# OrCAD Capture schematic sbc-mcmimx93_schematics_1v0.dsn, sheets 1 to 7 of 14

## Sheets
1 10  Ethernet connectos: size B; title: SBC-MCM93  10. Ethernet connectos; rev: 1.0; note: 8000233000; note: 17 HaYetsira Street; note: Yokneam Illit, Israel 2069208
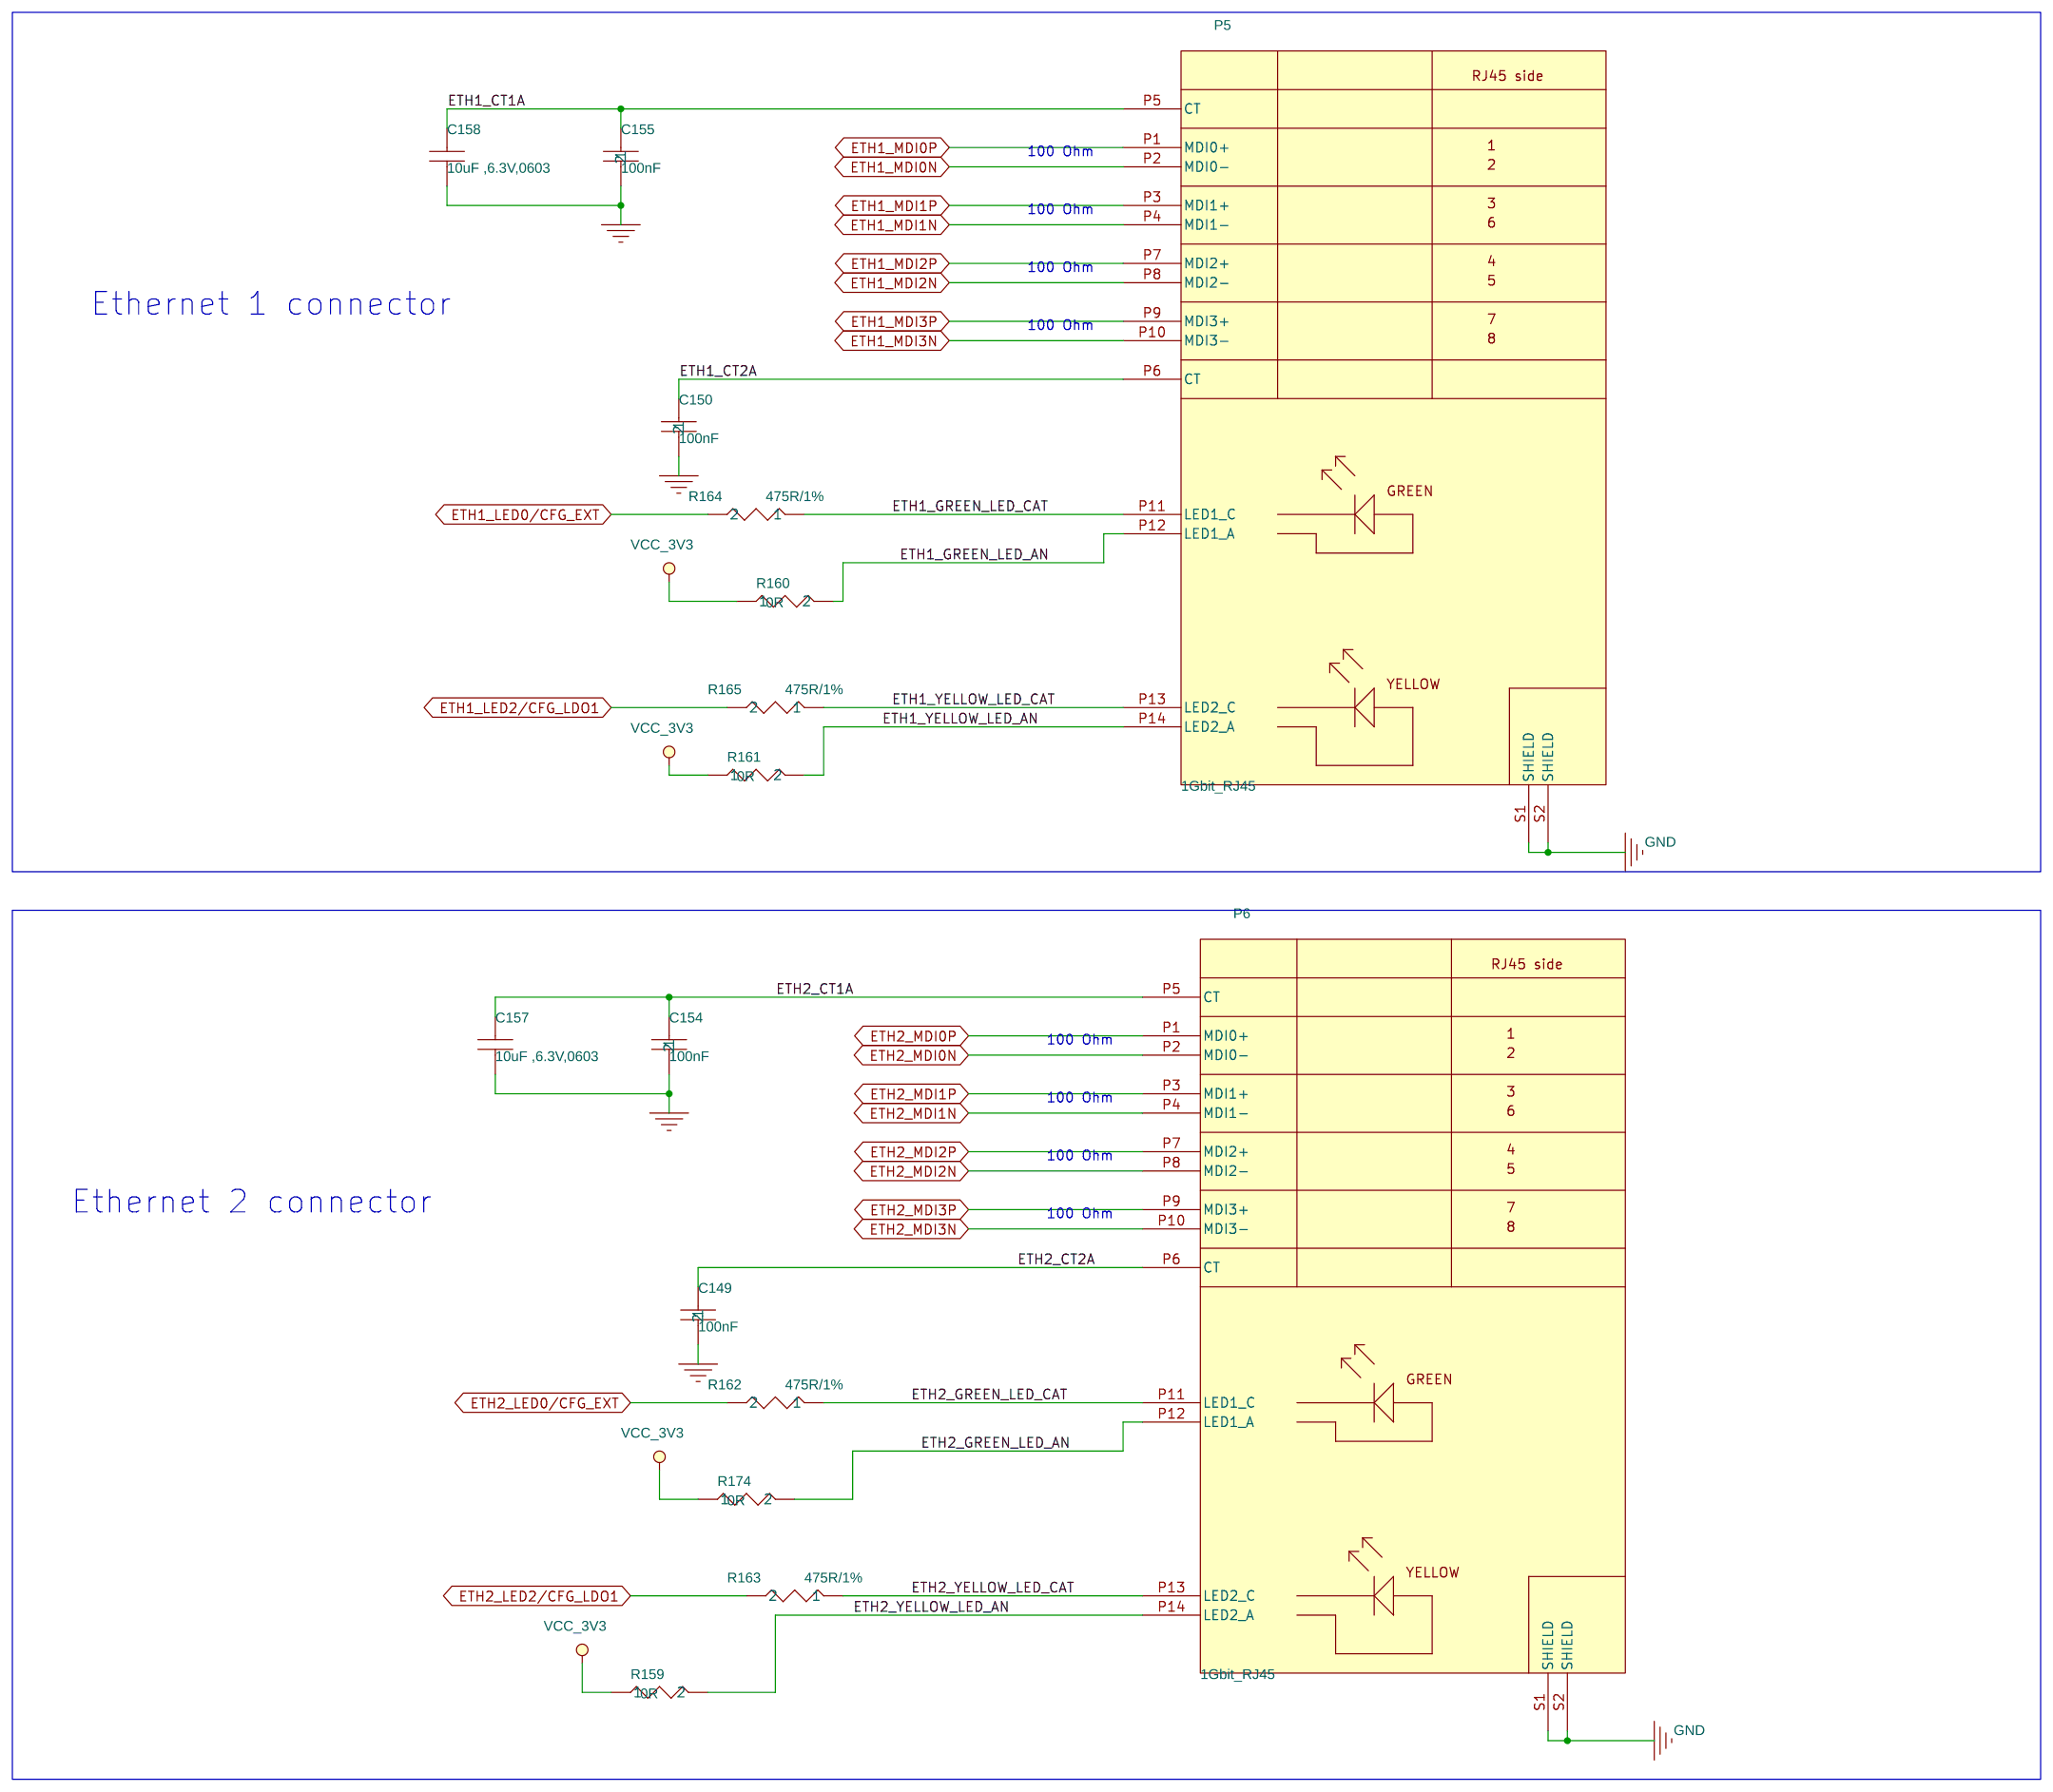
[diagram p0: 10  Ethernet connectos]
2 01 Index and Block Diagram: title: SBC-MCM93   01. INDEX AND BLOCK DIAGRAM
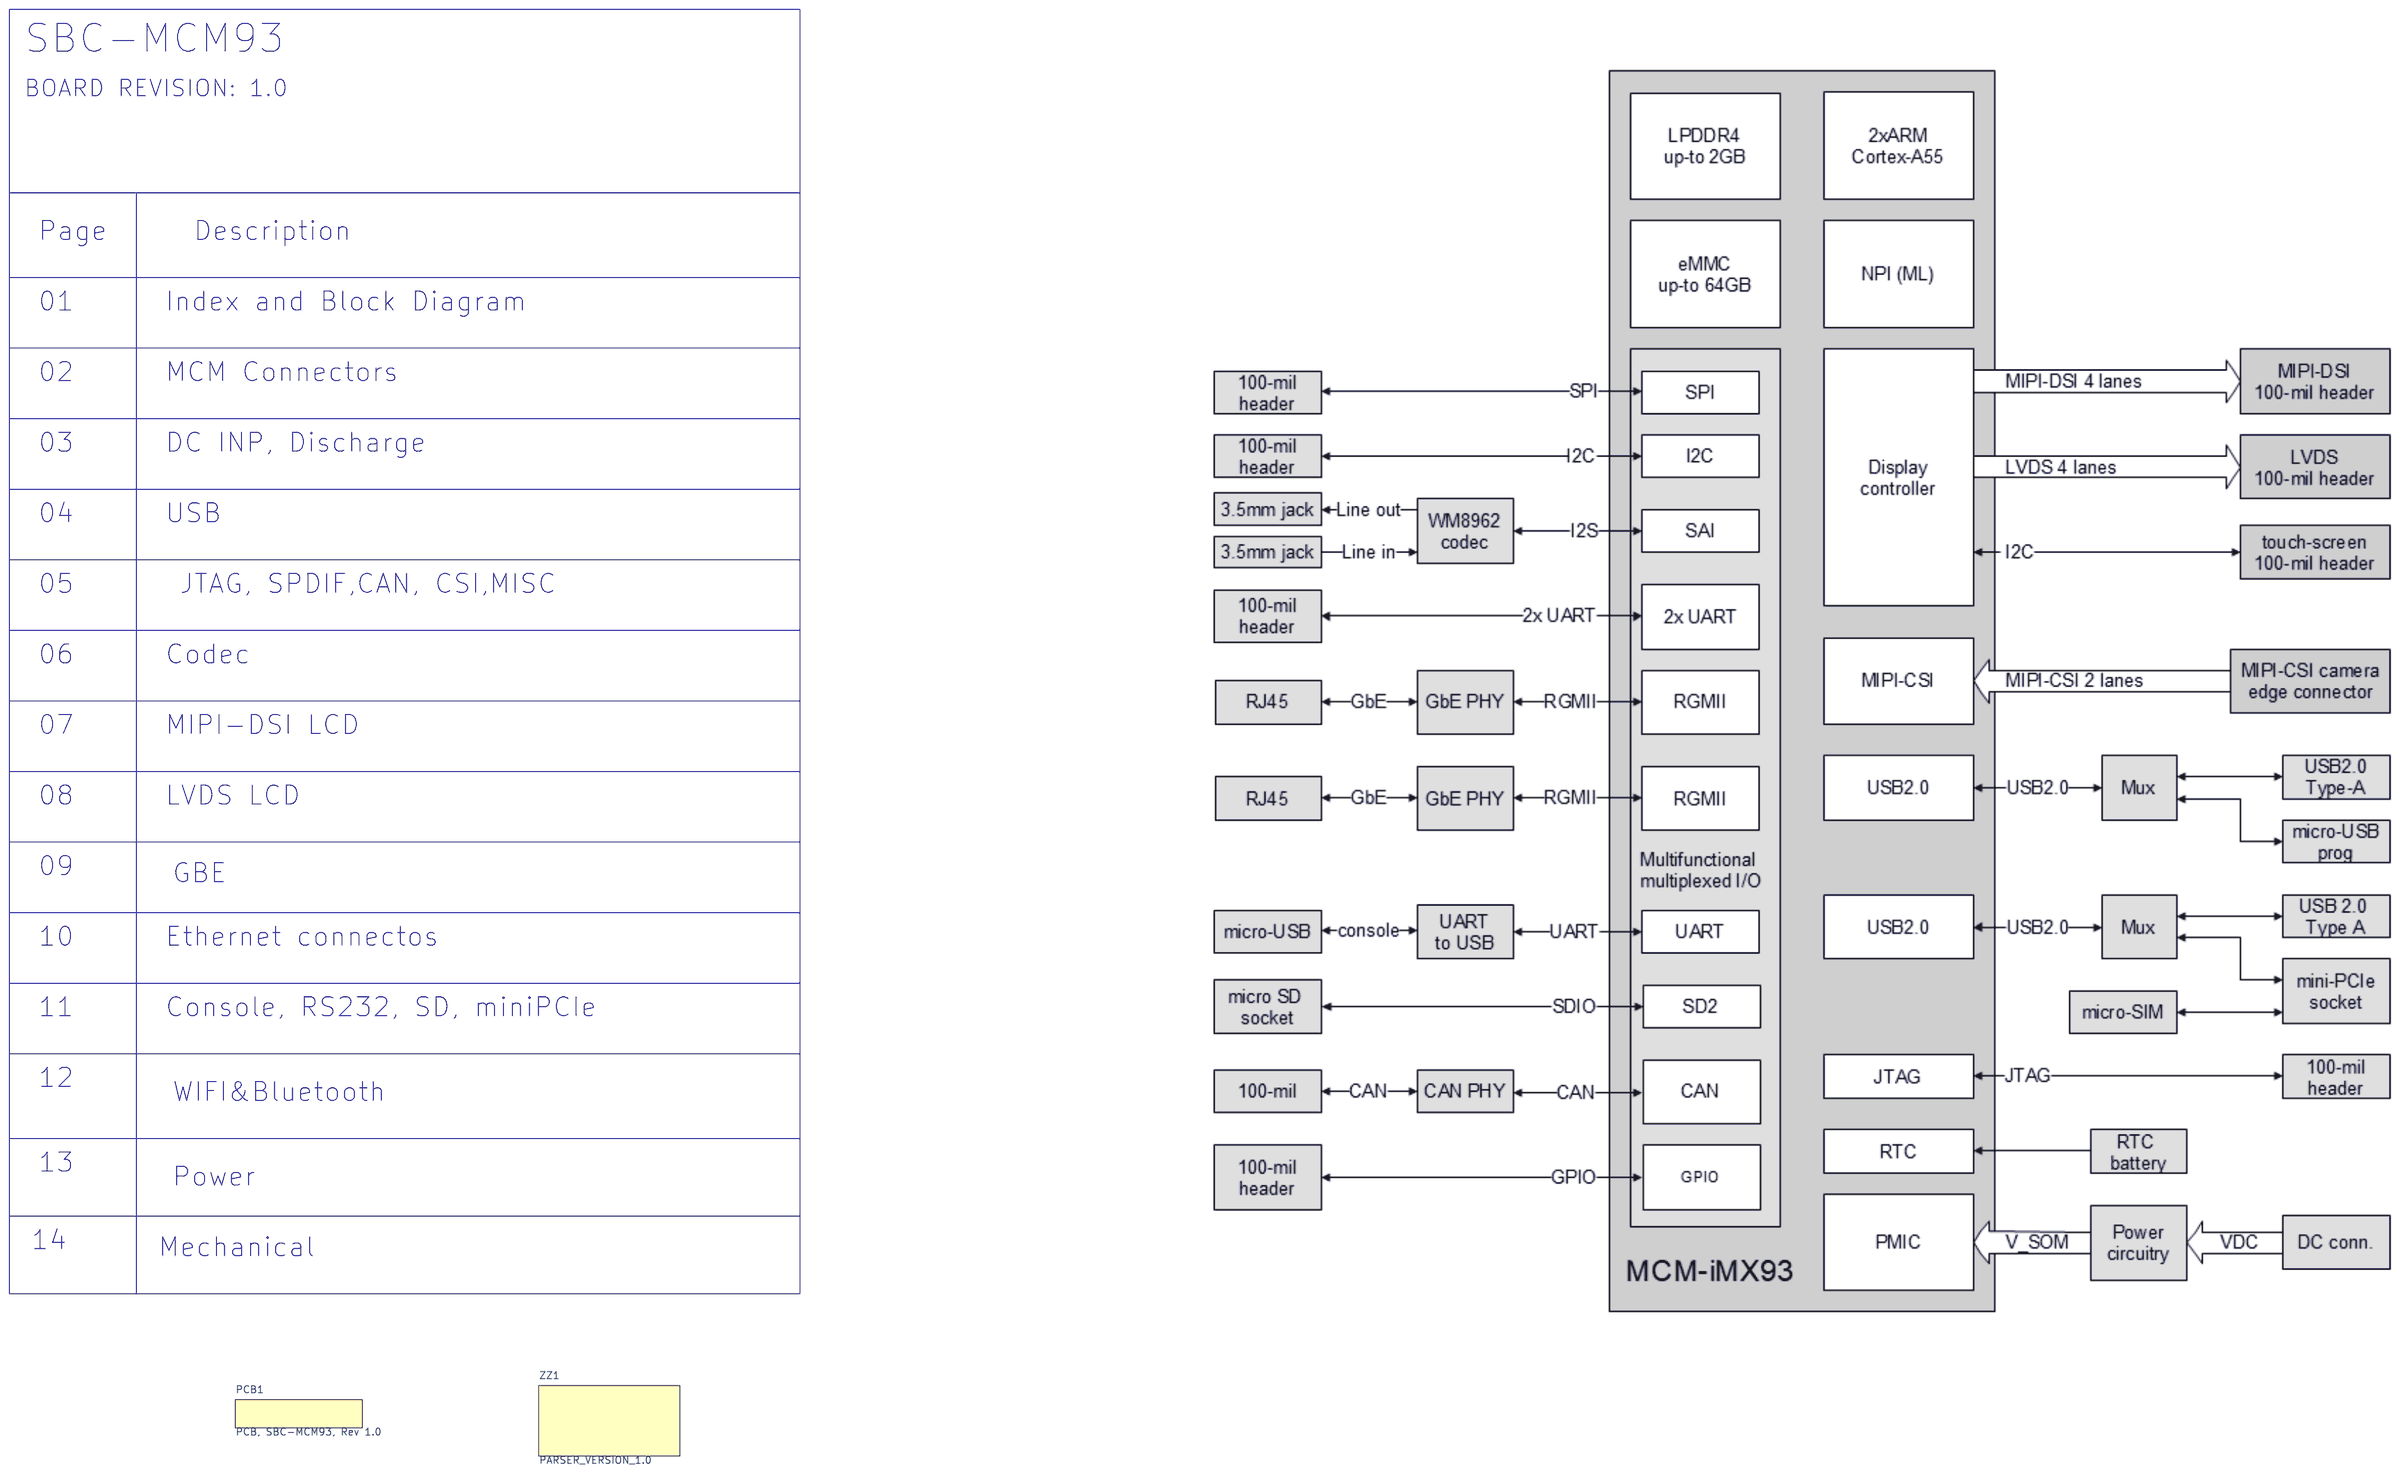
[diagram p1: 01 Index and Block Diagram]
3 03 DC INP, Discharge: size B; title: SBC-MCM93     03 DC INP, Discharge; company: CompuLab Ltd.  (972) 4 8238567
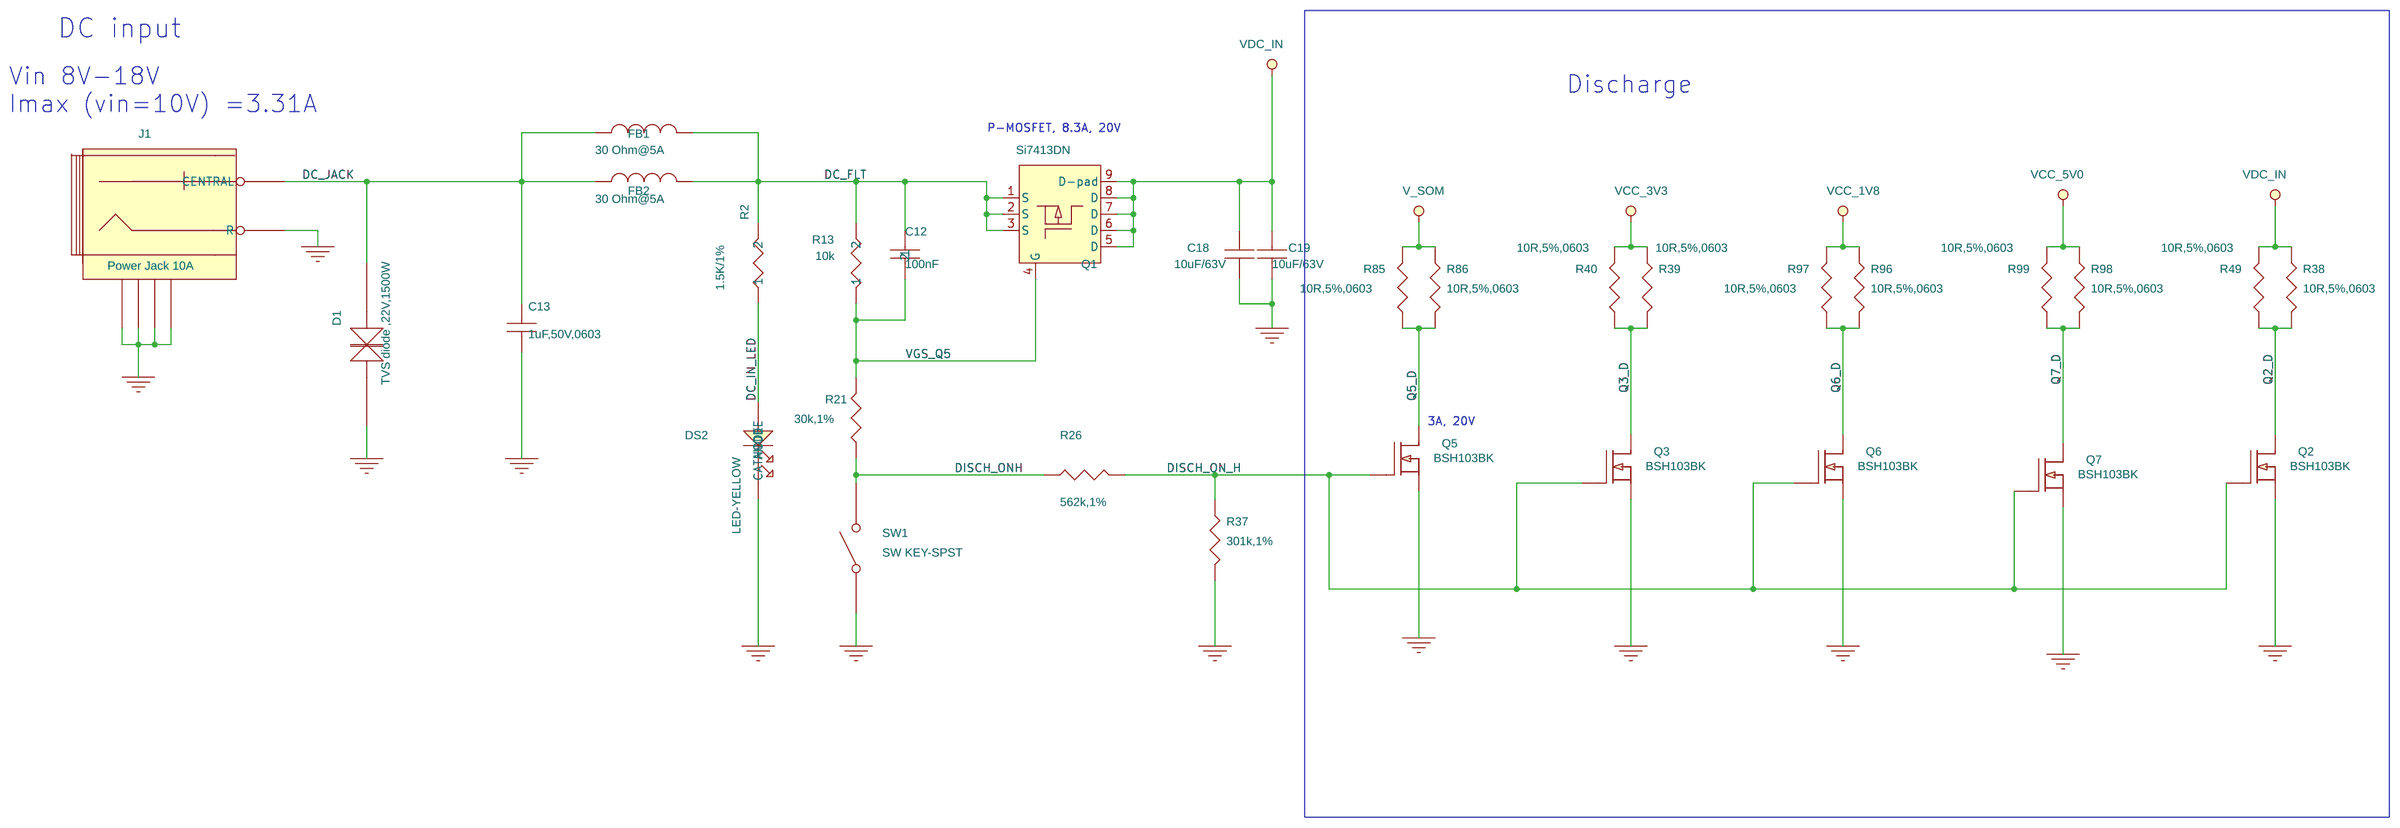
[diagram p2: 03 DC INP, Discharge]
4 02. Carrier Board interface MCM: size C; title: SBC-MCM93     02. Carrier Board interface MCM
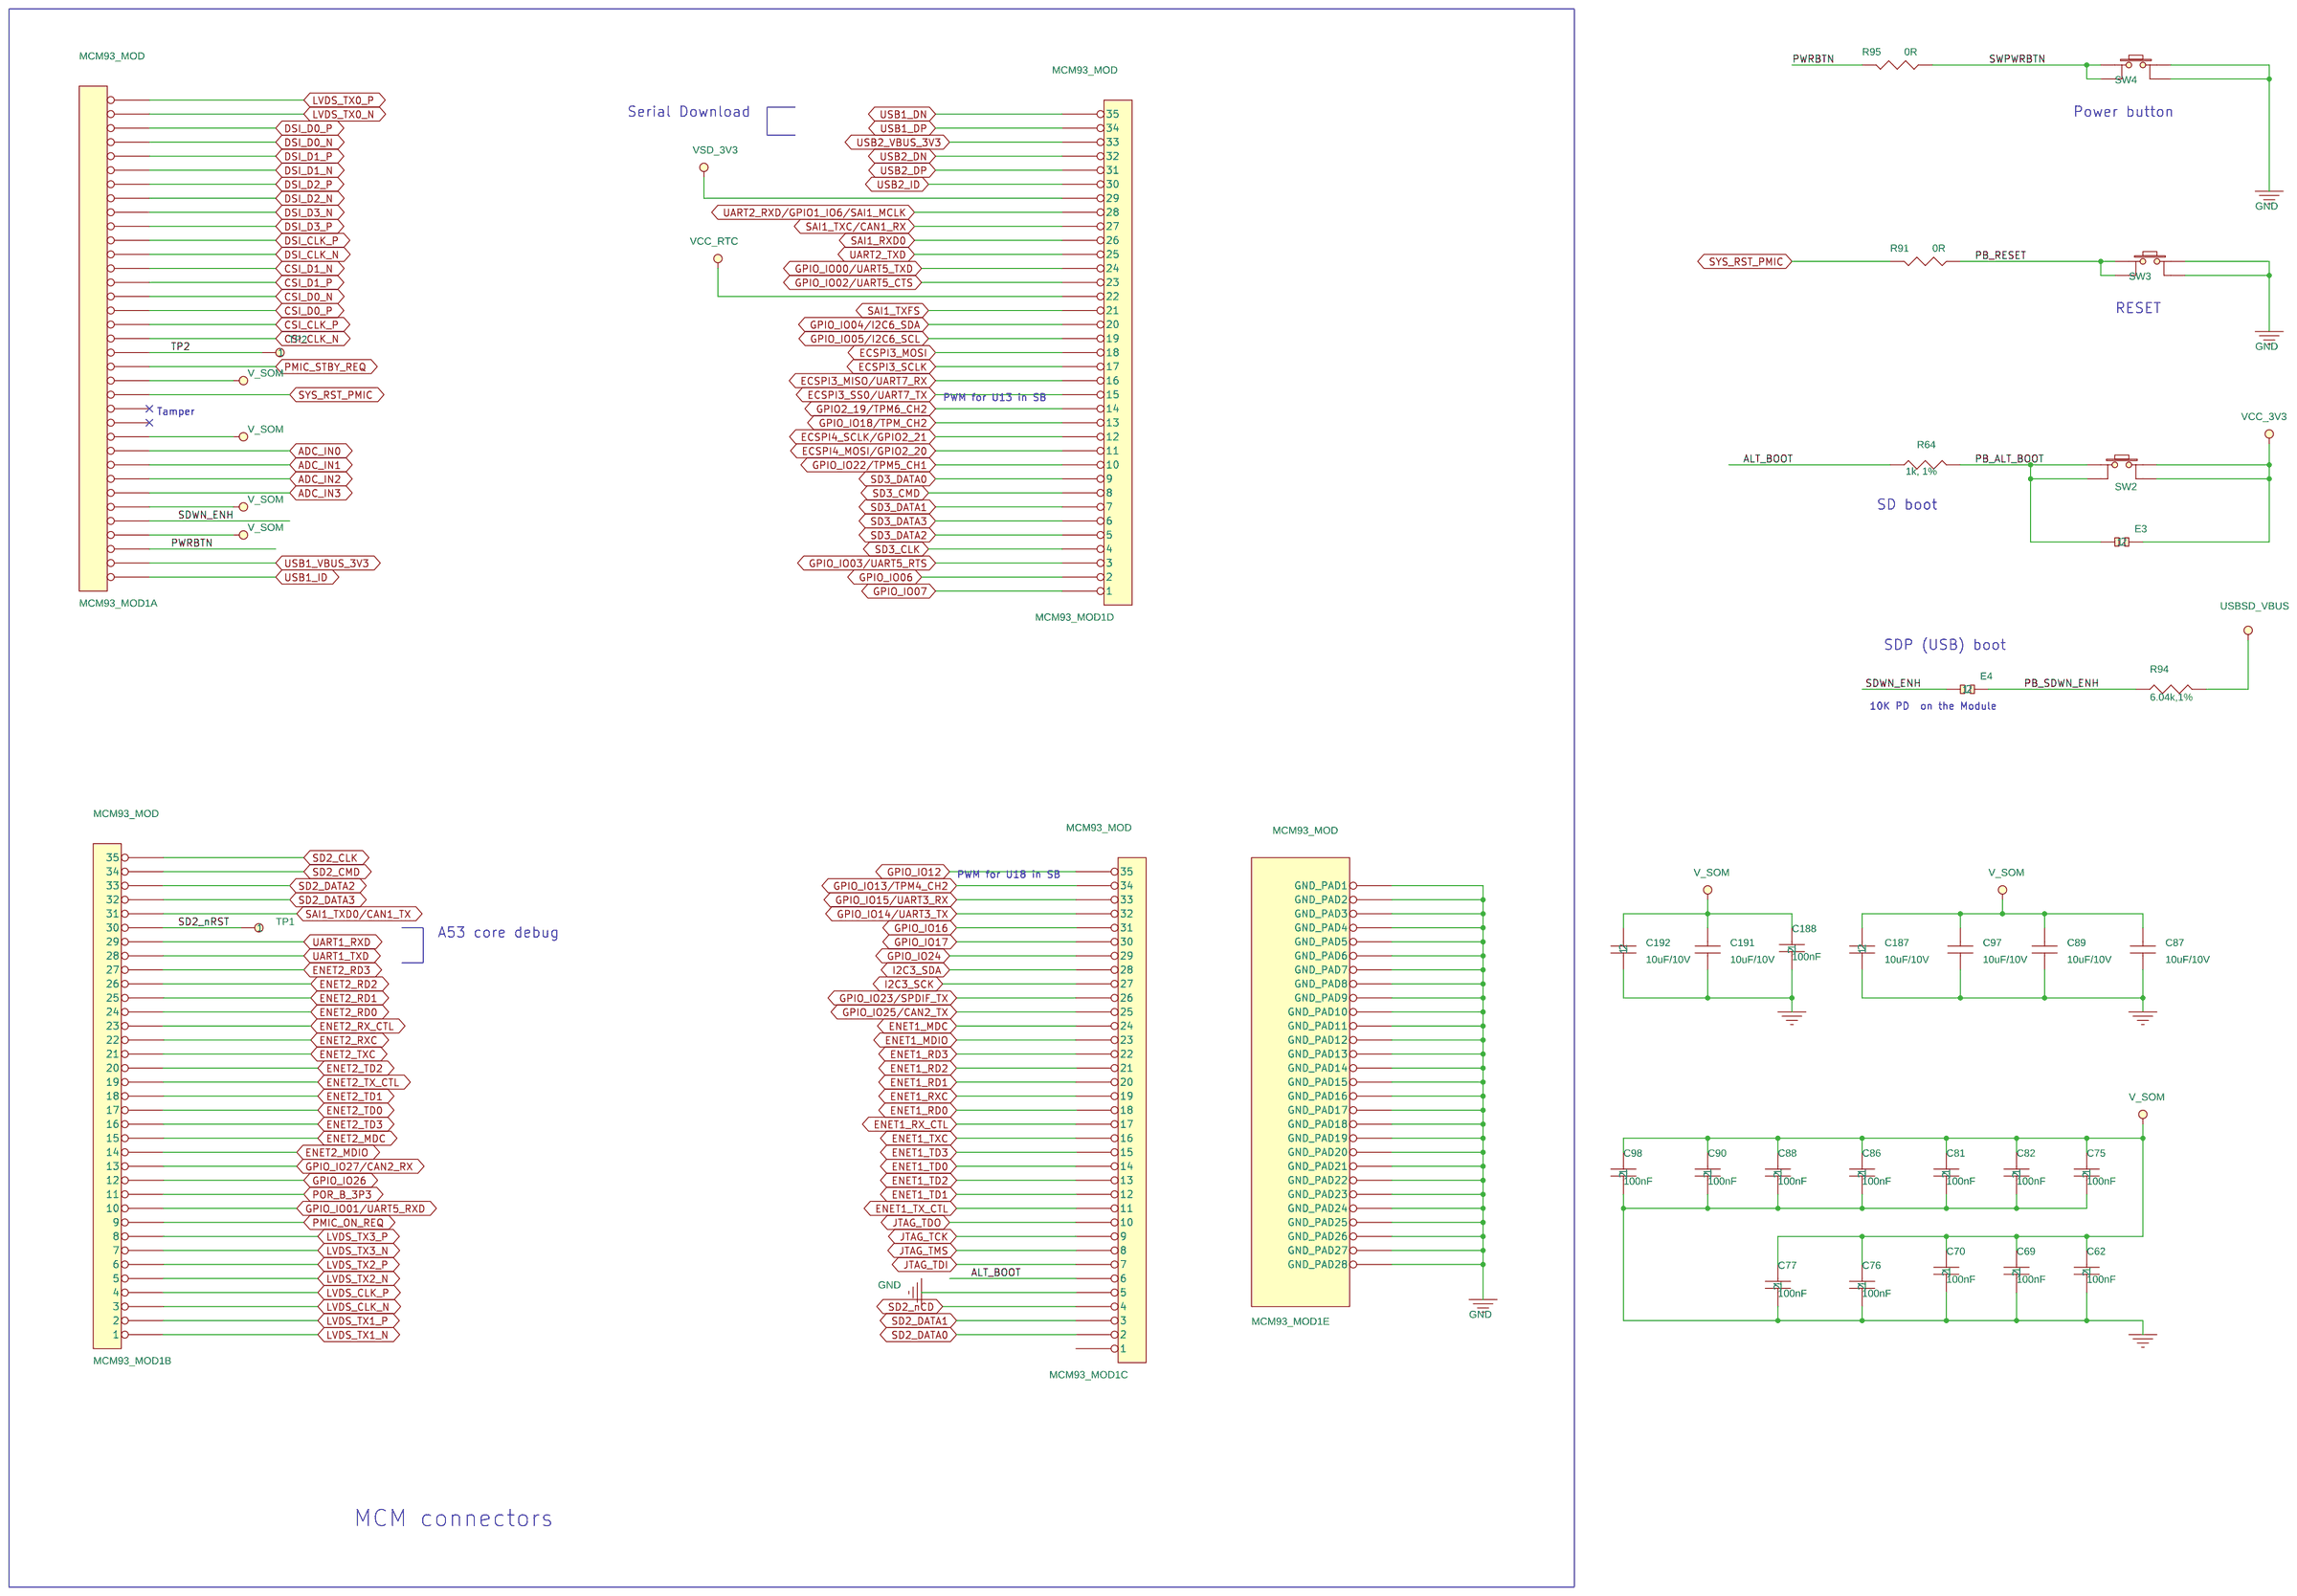
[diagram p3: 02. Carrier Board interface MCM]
5 04 USB: size C; title: SBC-MCM93    04. USB
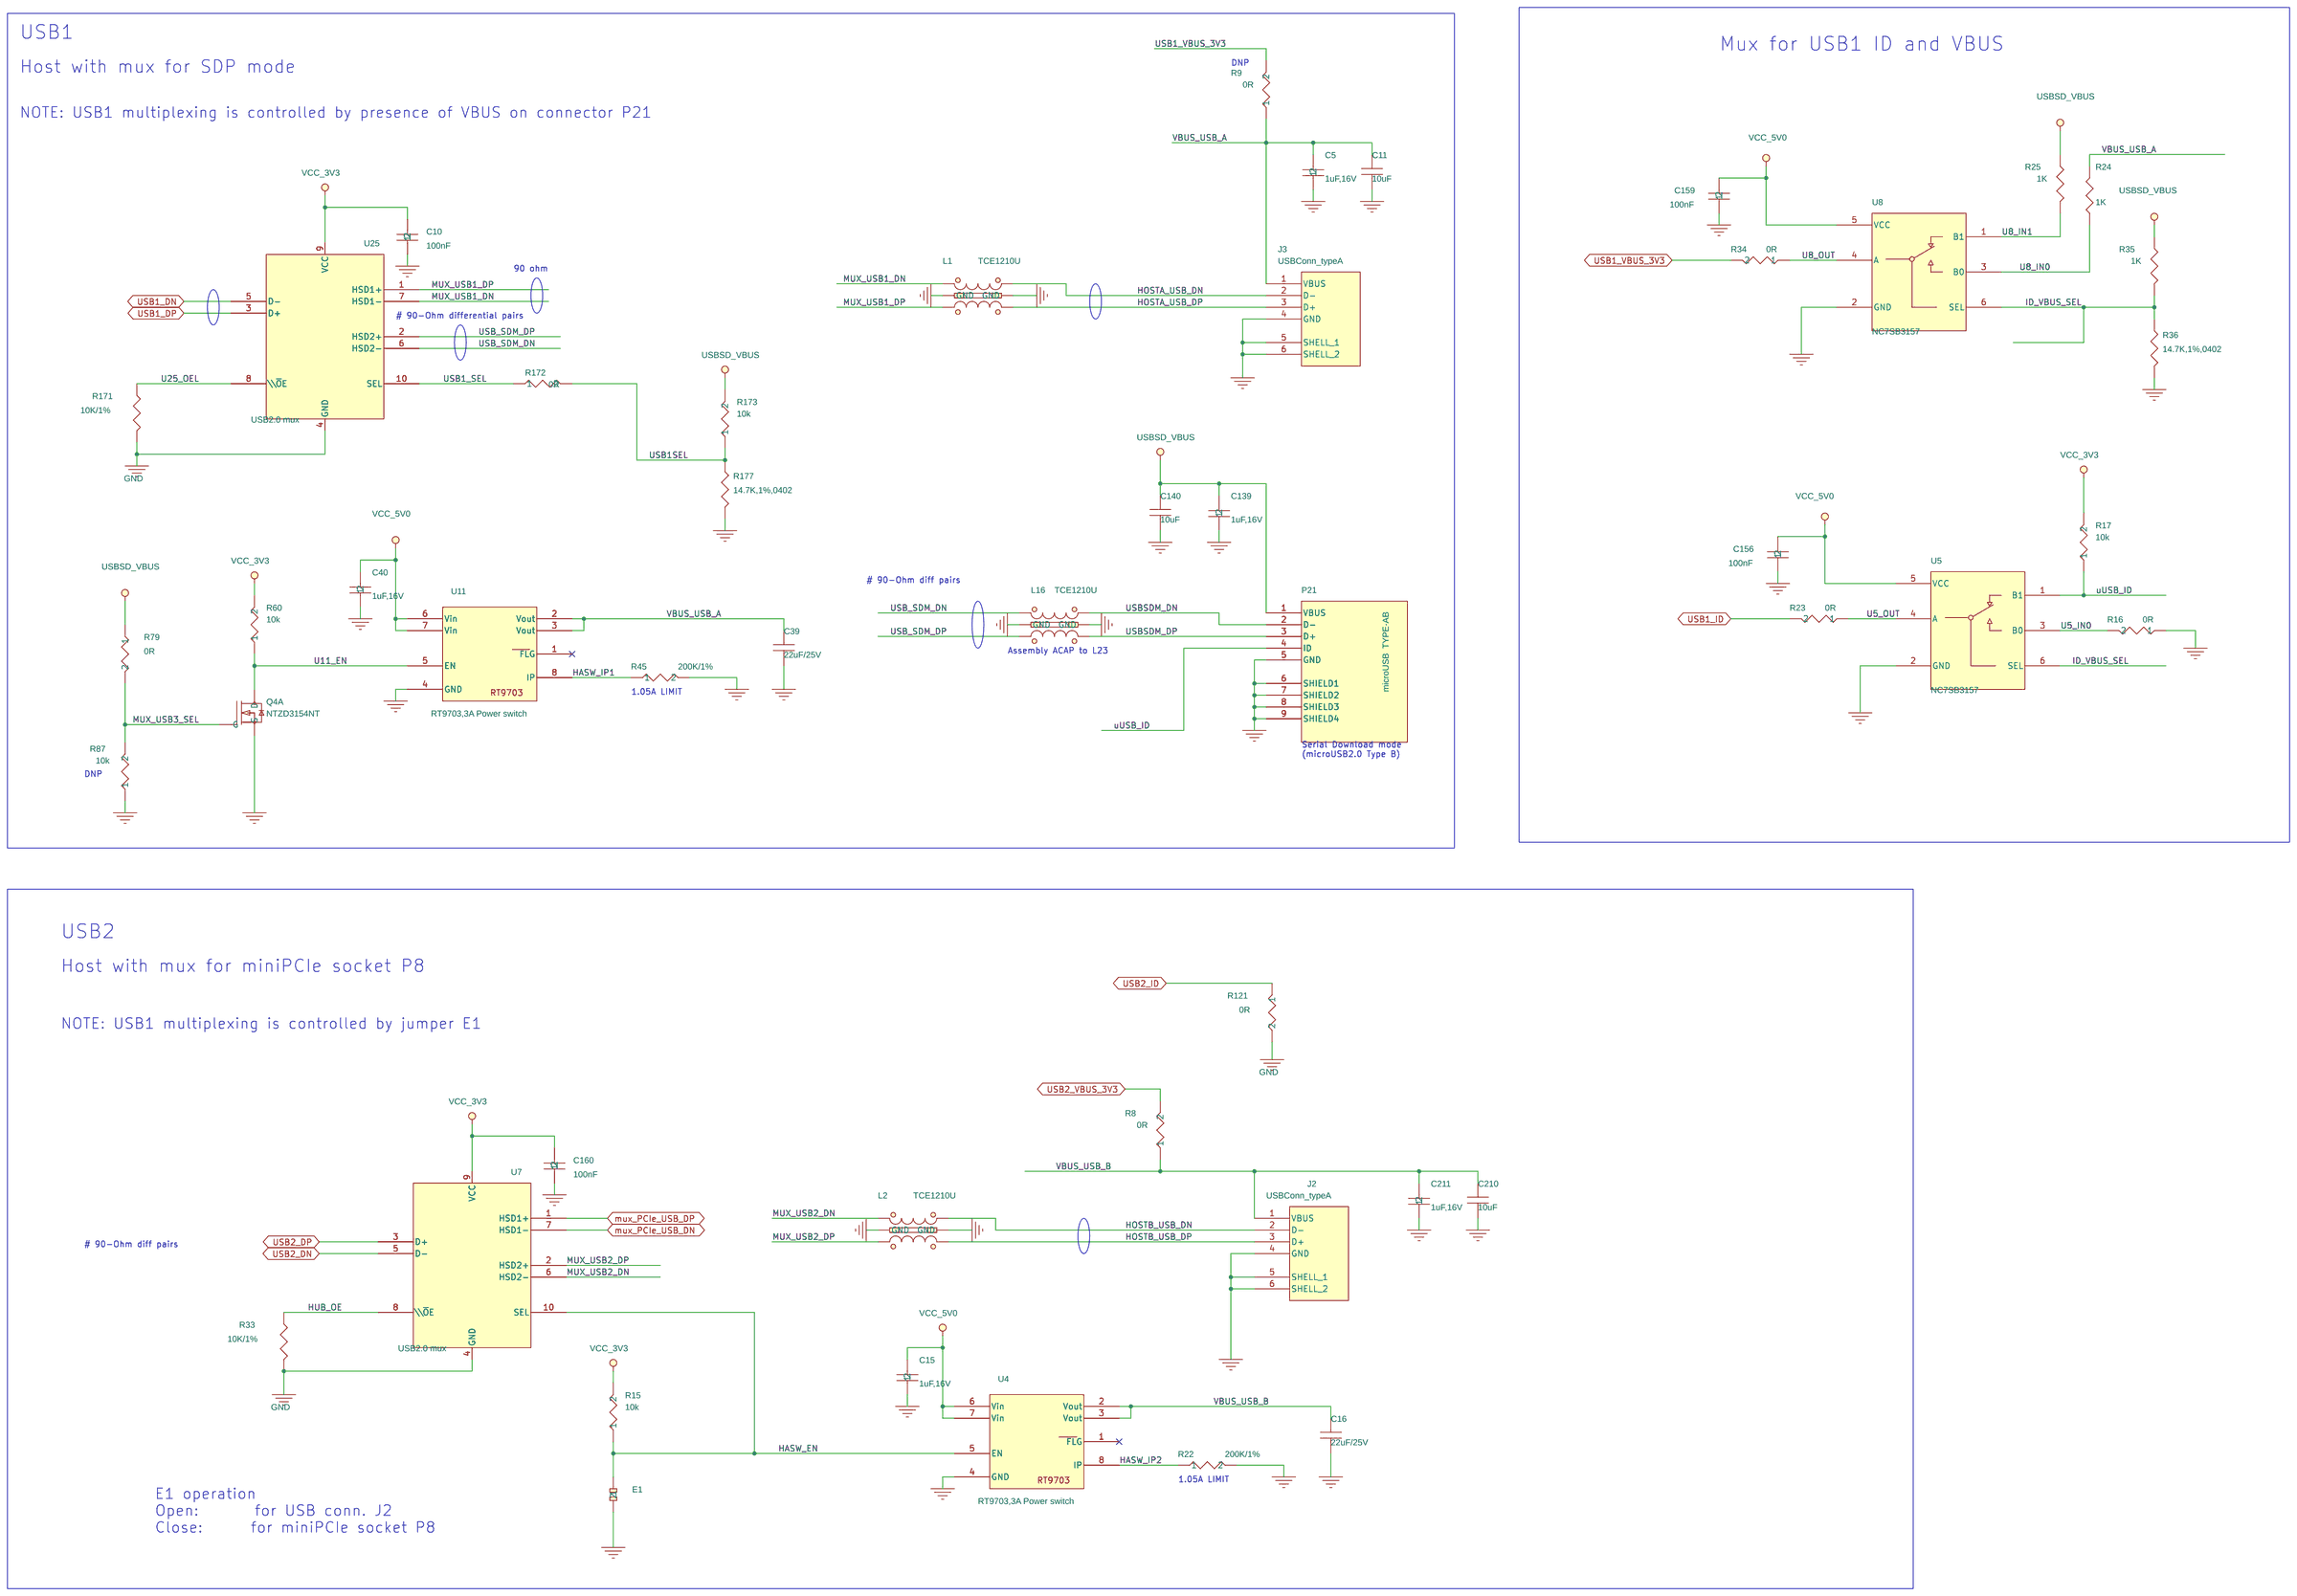
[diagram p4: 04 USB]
6 05  JTAG, SPDIF,CAN, CSI,MISC: size C; title: SBC-MCM93      05.  JTAG, SPDIF,CAN, CSI,MISC
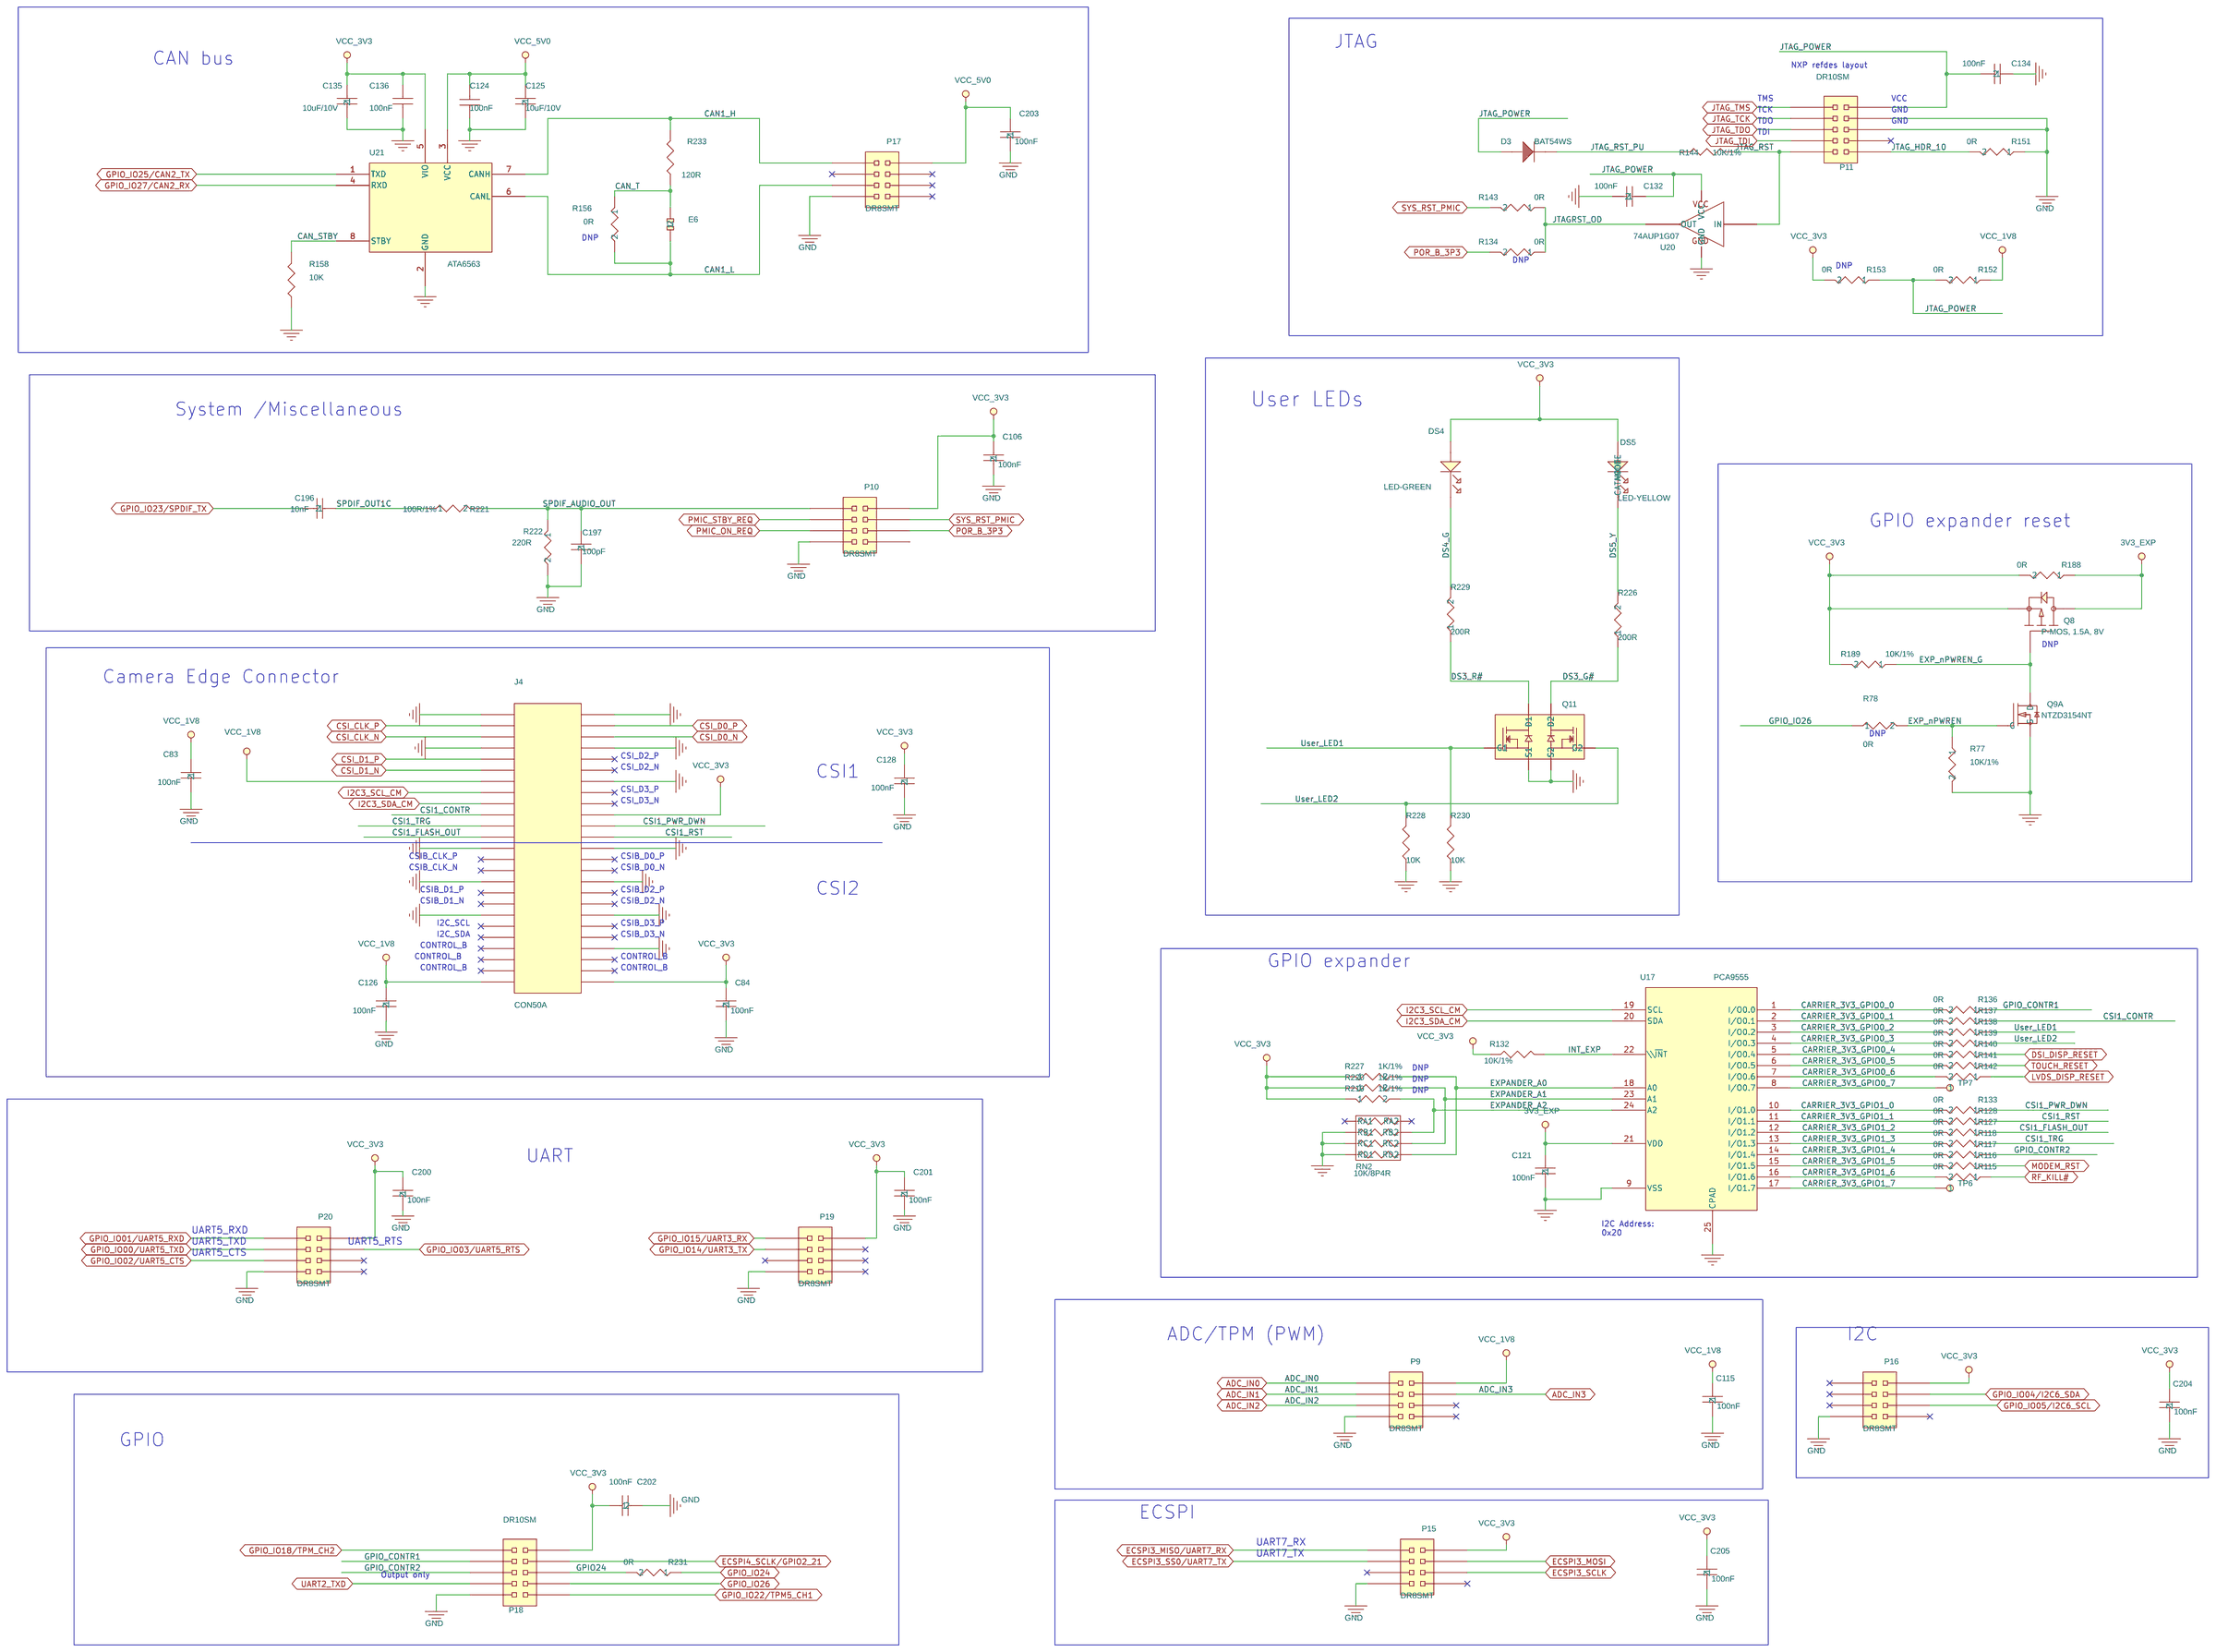
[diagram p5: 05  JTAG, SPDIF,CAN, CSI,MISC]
7 07 MIPI-DSI LCD: size B; title: SBC-MCM93  07. MIPI-DSI LCD
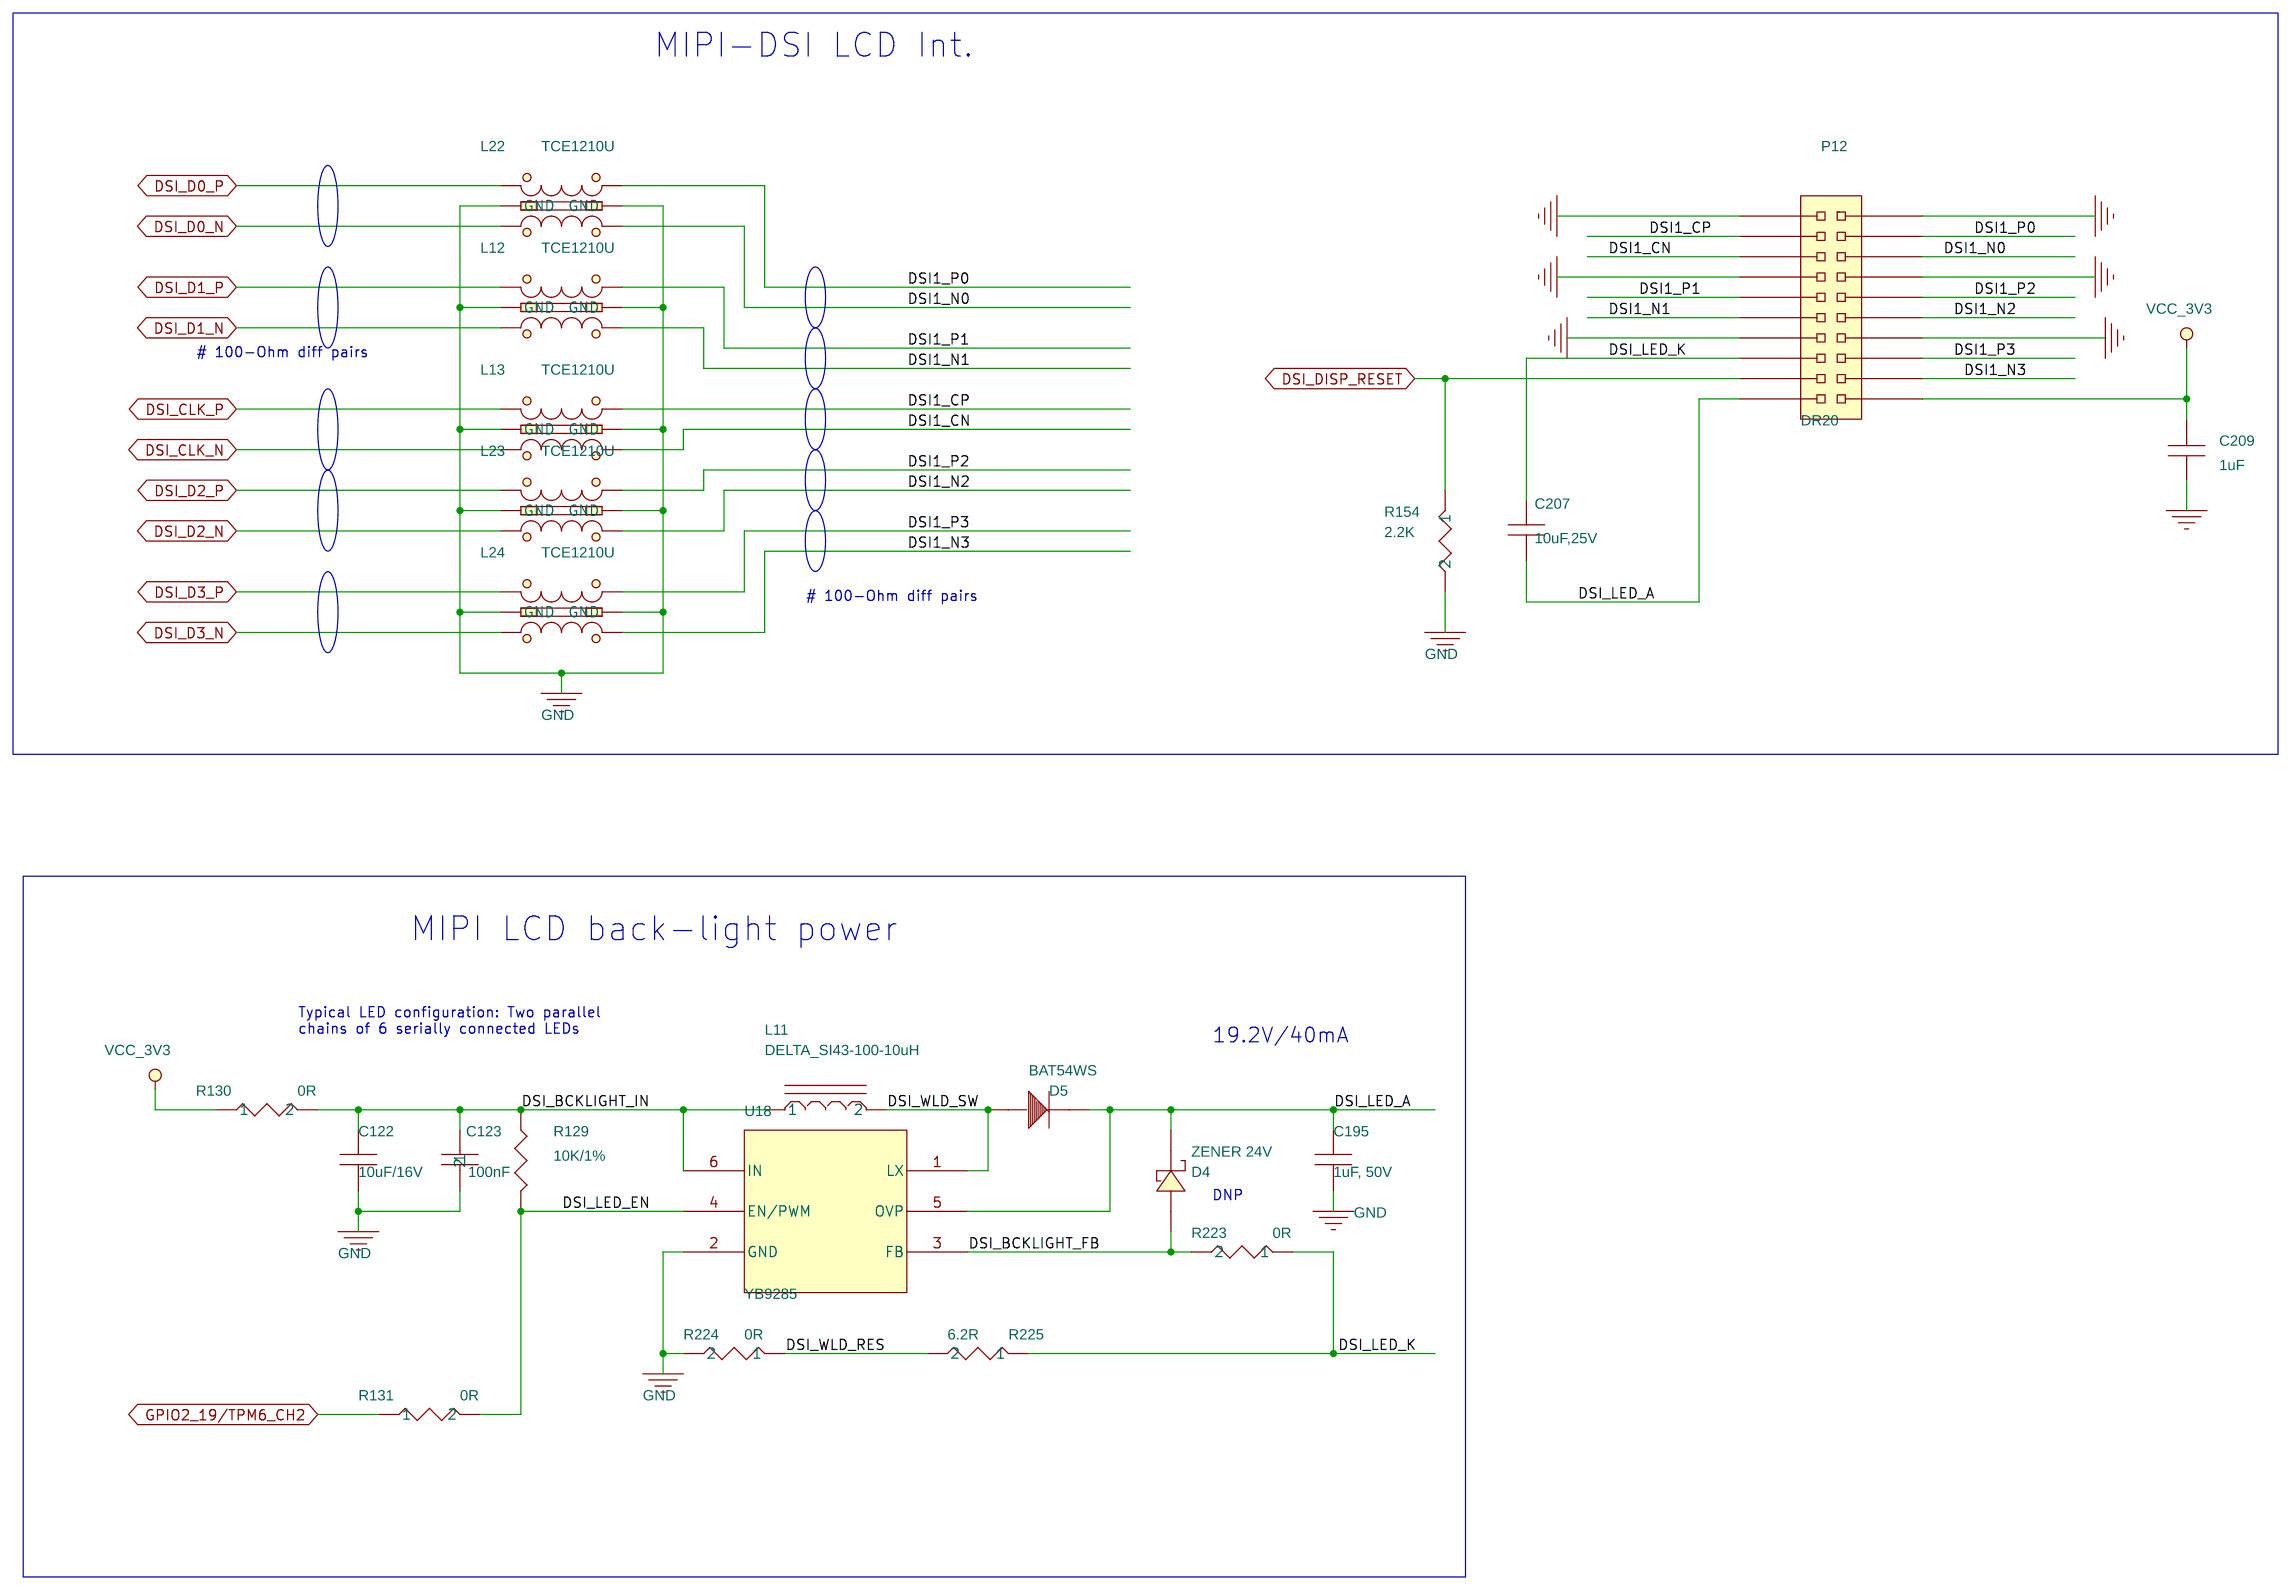
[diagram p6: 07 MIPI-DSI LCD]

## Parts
sheet 01 Index and Block Diagram
PCB1  PCB, SBC-MCM93, Rev 1.0
ZZ1  PARSER_VERSION_1.0
sheet 02. Carrier Board interface MCM
C62  100nF  [RC0402]
C69  100nF  [RC0402]
C70  100nF  [RC0402]
C75  100nF  [RC0402]
C76  100nF  [RC0402]
C77  100nF  [RC0402]
C81  100nF  [RC0402]
C82  100nF  [RC0402]
C86  100nF  [RC0402]
C87  10uF/10V  [0402]
C88  100nF  [RC0402]
C89  10uF/10V  [0402]
C90  100nF  [RC0402]
C97  10uF/10V  [0402]
C98  100nF  [RC0402]
C187  10uF/10V  [0402]
C188  100nF  [RC0402]
C191  10uF/10V  [0402]
C192  10uF/10V  [0402]
E3  HDR1X2  [1X2THHDR]
E4  HDR1X2  [1X2THHDR]
MCM93_MOD1  MCM93_MOD  (sections A,B,C,D,E)
R64  1k, 1%  [RC0402]
R91  0R  [RC0402]
R94  6.04k,1%  [RC0402]
R95  0R  [RC0402]
SW2  PushB  [TACTSW6x6SM]
SW3  PushB  [TACTSW6x6SM]
SW4  PushB  [TACTSW6x6SM]
TP1  TESTPOINT  [TESTPOINT]
TP2  TESTPOINT  [TESTPOINT]
sheet 03 DC INP, Discharge
C12  100nF  [RC0402]
C13  1uF,50V,0603  [RC0603]
C18  10uF/63V  [C1210H2_5]
C19  10uF/63V  [C1210H2_5]
D1  TVS diode ,22V,1500W  [DO-214AB]
DS2  LED-YELLOW  [LED-1206]
FB1  30 Ohm@5A  [FB0603]
FB2  30 Ohm@5A  [FB0603]
J1  Power Jack 10A  [PJ-0810-TH]
Q1  Si7413DN  [Powerpak1212-8]
Q2  BSH103BK  [SOT23]
Q3  BSH103BK  [SOT23]
Q5  BSH103BK  [SOT23]
Q6  BSH103BK  [SOT23]
Q7  BSH103BK  [SOT23]
R2  1.5K/1%  [RC0402]
R13  10k  [RC0402]
R21  30k,1%  [RC0402]
R26  562k,1%  [RC0402]
R37  301k,1%  [RC0402]
R38  10R,5%,0603  [RC0603]
R39  10R,5%,0603  [RC0603]
R40  10R,5%,0603  [RC0603]
R49  10R,5%,0603  [RC0603]
R85  10R,5%,0603  [RC0603]
R86  10R,5%,0603  [RC0603]
R96  10R,5%,0603  [RC0603]
R97  10R,5%,0603  [RC0603]
R98  10R,5%,0603  [RC0603]
R99  10R,5%,0603  [RC0603]
SW1  SW KEY-SPST
sheet 04 USB
C5  1uF,16V  [RC0402]
C10  100nF  [RC0402]
C11  10uF  [C0603-08]
C15  1uF,16V  [RC0402]
C16  22uF/25V  [C0805]
C39  22uF/25V  [C0805]
C40  1uF,16V  [RC0402]
C139  1uF,16V  [RC0402]
C140  10uF  [C0603-08]
C156  100nF  [RC0402]
C159  100nF  [RC0402]
C160  100nF  [RC0402]
C210  10uF  [C0603-08]
C211  1uF,16V  [RC0402]
E1  HDR1X2  [1X2THHDR]
J2  USBConn_typeA  [USB-A-SM]
J3  USBConn_typeA  [USB-A-SM]
L1  TCE1210U  [EMI1012-ESD]
L2  TCE1210U  [EMI1012-ESD]
L16  TCE1210U  [EMI1012-ESD]
P21  microUSB  TYPE-AB  [MICRO-USB-AB-RA-SM]
R8  0R  [RC0402]
R9  0R  [RC0402]
R15  10k  [RC0402]
R16  0R  [RC0402]
R17  10k  [RC0402]
R22  200K/1%  [RC0402]
R23  0R  [RC0402]
R24  1K  [RC0402]
R25  1K  [RC0402]
R33  10K/1%  [RC0402]
R34  0R  [RC0402]
R35  1K  [RC0402]
R36  14.7K,1%,0402  [RC0402]
R45  200K/1%  [RC0402]
R60  10k  [RC0402]
R79  0R  [RC0402]
R87  10k  [RC0402]
R121  0R  [RC0402]
R171  10K/1%  [RC0402]
R172  0R  [RC0402]
R173  10k  [RC0402]
R177  14.7K,1%,0402  [RC0402]
U4  RT9703,3A Power switch  [SO8-150]
U5  NC7SB3157  [SC70-6]
U7  USB2.0 mux  [MO-255U1418E]
U8  NC7SB3157  [SC70-6]
U11  RT9703,3A Power switch  [SO8-150]
U25  USB2.0 mux  [MO-255U1418E]
sheet 05  JTAG, SPDIF,CAN, CSI,MISC
C83  100nF  [RC0402]
C84  100nF  [RC0402]
C106  100nF  [RC0402]
C115  100nF  [RC0402]
C121  100nF  [RC0402]
C124  100nF  [RC0402]
C125  10uF/10V  [RC0402]
C126  100nF  [RC0402]
C128  100nF  [RC0402]
C132  100nF  [RC0402]
C134  100nF  [RC0402]
C135  10uF/10V  [RC0402]
C136  100nF  [RC0402]
C196  10nF  [RC0402]
C197  100pF  [RC0402]
C200  100nF  [RC0402]
C201  100nF  [RC0402]
C202  100nF  [RC0402]
C203  100nF  [RC0402]
C204  100nF  [RC0402]
C205  100nF  [RC0402]
D3  BAT54WS  [SOD-323]
DS4  LED-GREEN  [LED-1206]
DS5  LED-YELLOW  [LED-1206]
E6  HDR1X2  [1X2THHDR]
J4  CON50A
P9  DR8SMT  [2X4SMHDR]
P10  DR8SMT  [2X4SMHDR]
P11  DR10SM  [2X5SMHDR]
P15  DR8SMT  [2X4SMHDR]
P16  DR8SMT  [2X4SMHDR]
P17  DR8SMT  [2X4SMHDR]
P18  DR10SM  [2X5SMHDR]
P19  DR8SMT  [2X4SMHDR]
P20  DR8SMT  [2X4SMHDR]
Q8  P-MOS, 1.5A, 8V  [SOT23]
Q9  NTZD3154NT  [SOT-563-6]  (section A)
Q11  0.5A,20V,Vgs max 6V  [SOT-563-6]
R77  10K/1%  [RC0402]
R78  0R  [RC0402]
R115  0R  [RC0402]
R116  0R  [RC0402]
R117  0R  [RC0402]
R118  0R  [RC0402]
R127  0R  [RC0402]
R128  0R  [RC0402]
R132  10K/1%  [RC0402]
R133  0R  [RC0402]
R134  0R  [RC0402]
R136  0R  [RC0402]
R137  0R  [RC0402]
R138  0R  [RC0402]
R139  0R  [RC0402]
R140  0R  [RC0402]
R141  0R  [RC0402]
R142  0R  [RC0402]
R143  0R  [RC0402]
R144  10K/1%  [RC0402]
R151  0R  [RC0402]
R152  0R  [RC0402]
R153  0R  [RC0402]
R156  0R  [RC0402]
R158  10K  [RC0402]
R188  0R  [RC0402]
R189  10K/1%  [RC0402]
R219  1K/1%  [RC0402]
R220  1K/1%  [RC0402]
R221  100R/1%  [RC0402]
R222  220R  [RC0402]
R226  200R  [RC0402]
R227  1K/1%  [RC0402]
R228  10K  [RC0402]
R229  200R  [RC0402]
R230  10K  [RC0402]
R231  0R  [RC0402]
R233  120R  [RC0402]
RN2  10K/8P4R  [RESNET8P0805]
TP6  TESTPOINT SMT  [TESTPOINT]
TP7  TESTPOINT SMT  [TESTPOINT]
U17  PCA9555  [QFN4x4-24]
U20  74AUP1G07  [SC70]
U21  ATA6563  [SOI8-150]
sheet 07 MIPI-DSI LCD
C122  10uF/16V  [RC0603]
C123  100nF  [RC0402]
C195  1uF, 50V  [RC0603]
C207  10uF,25V  [RC0603]
C209  1uF  [RC0402]
D4  ZENER 24V  [SOD-123]
D5  BAT54WS  [SOD-323]
L11  DELTA_SI43-100-10uH  [IND4x4x2_5]
L12  TCE1210U  [EMI1012-ESD]
L13  TCE1210U  [EMI1012-ESD]
L22  TCE1210U  [EMI1012-ESD]
L23  TCE1210U  [EMI1012-ESD]
L24  TCE1210U  [EMI1012-ESD]
P12  DR20  [2X12THHDR]
R129  10K/1%  [RC0402]
R130  0R  [RC0402]
R131  0R  [RC0402]
R154  2.2K  [RC0402]
R223  0R  [RC0402]
R224  0R  [RC0402]
R225  6.2R  [RC0402]
U18  YB9285  [SOT23-6L]
sheet 10  Ethernet connectos
C149  100nF  [RC0402]
C150  100nF  [RC0402]
C154  100nF  [RC0402]
C155  100nF  [RC0402]
C157  10uF ,6.3V,0603  [RC0603]
C158  10uF ,6.3V,0603  [RC0603]
P5  1Gbit_RJ45  [DUSBRJ-1G]
P6  1Gbit_RJ45  [DUSBRJ-1G]
R159  0R  [RC0402]
R160  0R  [RC0402]
R161  0R  [RC0402]
R162  475R/1%  [RC0402]
R163  475R/1%  [RC0402]
R164  475R/1%  [RC0402]
R165  475R/1%  [RC0402]
R174  0R  [RC0402]
sheet 13 Power
Q4  NTZD3154NT  [SOT-563-6]  (sections A,B)

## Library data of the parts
PCB1 = PCB,_EM-X270_Rev_1_0.1: CLABCONF0: =SBC-MCM93; P/N: 188C04590
ZZ1 = PARSER_VERSION_1_1.0: CLABCONF0: DNP
C62 C106 = 100nF,_10V,_X7R,_10%,_0402_7: CLABCONF0: =SBC-MCM93
C69 C84 = 100nF,_10V,_X7R,_10%,_0402_6: CLABCONF0: =SBC-MCM93
C70 C201 = 100nF,_10V,_X7R,_10%,_0402_8: CLABCONF0: =SBC-MCM93
C75 C126 = 100nF,_10V,_X7R,_10%,_0402_5: CLABCONF0: =SBC-MCM93
C76 C155 C200 = 100nF,_10V,_X7R,_10%,_0402_1: CLABCONF0: =SBC-MCM93
C77 C128 C150 = 100nF,_10V,_X7R,_10%,_0402_2: CLABCONF0: =SBC-MCM93
C81 C134 = 100nF,_10V,_X7R,_10%,_0402_11: CLABCONF0: =SBC-MCM93
C82 C115 = 100nF,_10V,_X7R,_10%,_0402_12: CLABCONF0: =SBC-MCM93
C86 C204 = 100nF,_10V,_X7R,_10%,_0402_4: CLABCONF0: =SBC-MCM93
C87 = 10uF,6.3V,0603,20%X5R_1: CLABCONF0: =SBC-MCM93; P/N: 151B10600S
C88 C154 C205 = 100nF,_10V,_X7R,_10%,_0402_3: CLABCONF0: =SBC-MCM93
C89 = 10uF,6.3V,0603,20%X5R_3: CLABCONF0: =SBC-MCM93; P/N: 151B10600S
C90 C202 = 100nF,_10V,_X7R,_10%,_0402_9: CLABCONF0: =SBC-MCM93
C97 = 10uF,6.3V,0603,20%X5R_2: CLABCONF0: =SBC-MCM93; P/N: 151B10600S
C12 C98 C121 C123 C149 = 100nF,_10V,_X7R,_10%,_0402: CLABCONF0: =SBC-MCM93
C125 C187 = 10uF_10V_20%_0402_1: CLABCONF0: =SBC-MCM93
C188 C203 = 100nF,_10V,_X7R,_10%,_0402_10: CLABCONF0: =SBC-MCM93
C191 = 10uF,6.3V,0603,20%X5R: CLABCONF0: =SBC-MCM93; P/N: 151B10600S
C135 C192 = 10uF_10V_20%_0402: CLABCONF0: =SBC-MCM93
E1 E3 E6 = HDR_1x2_100MIL_TH_JUMPER: CLABCONF0: =SBC-MCM93
E4 = HDR_1x2_100MIL_TH_JUMPER_1: CLABCONF0: =SBC-MCM93
MCM93_MOD1 = MCM93_MOD: CLABCONF0: 503M015410= CDD2N32; CLABCONF1: 503M015420 = CDD1N16; P/N: 503M015350
R24 R25 R35 R64 = RESISTOR: CLABCONF0: =SBC-MCM93; P/N: 161C10011S
R91 = 0R,_0402_0: CLABCONF0: =SBC-MCM93; P/N: 161C00005S
R94 = RESISTOR: CLABCONF0: =SBC-MCM93; P/N: 161C60411S; Part Name: Res., 6.04K, 1%, 0402, 1/16W
R95 = 0R,_0402_0_1: CLABCONF0: =SBC-MCM93; P/N: 161C00005S
SW2-SW4 = TACT_SW_6x6mm_SMT: CLABCONF0: =SBC-MCM93
TP1 TP2 = TESTPOINT: CLABCONF0: DNP; P/N: TESTPOINT_SMT
C13 = CAP_NP: CLABCONF0: =SBC-MCM93; P/N: 151D10510S; Part Name: Cap., 1uF, 50V, X5R/X7R, 10%, 0603
C18 C19 = 22uF_25V: CLABCONF0: =SBC-MCM93; P/N: 151E10680S
D1 = Diode_,TVS_,15V,1500W_0: CLABCONF0: =SBC-MCM93; P/N: 132D10030S
DS2 DS5 = LED-RED_1206: CLABCONF0: =SBC-MCM93; P/N: 139A10110S
FB1 = Ferrite_bead_,_30_Ohm@5A_1: CLABCONF0: =SBC-MCM93
FB2 = Ferrite_bead_,_30_Ohm@5A: CLABCONF0: =SBC-MCM93
J1 = DC_Jack_,5.5_2.5,10A,20V: CLABCONF0: =SBC-MCM93
Q1 = Si7413DN: CLABCONF0: =SBC-MCM93
Q2 Q3 Q5-Q7 = MOSFET_N_SOT23: CLABCONF0: =SBC-MCM93; P/N: 131D10160S
R2 = 1.5K_1%,_0402: CLABCONF0: =SBC-MCM93
R13 = 1M_,5%,_0402: CLABCONF0: =SBC-MCM93; P/N: 161C10021S
R21 = RESISTOR: CLABCONF0: =SBC-MCM93; P/N: 161C30021S; Part Name: Res., 30K, 1%, 0402, 1/16W
R26 = RESISTOR: CLABCONF0: =SBC-MCM93; P/N: 161C56231S; Part Name: Res., 562K, 1%, 0402, 1/16W
R37 = RESISTOR: CLABCONF0: =SBC-MCM93; P/N: 161C30131S; Part Name: Res., 301K, 1%, 0402, 1/16W
R38-R40 R49 R85 R86 R96-R99 = RESISTOR: CLABCONF0: =SBC-MCM93; P/N: 161D10R05S; Part Name: Res., 10R, 5%, 0603
SW1 = SW_KEY-SPST: CLABCONF0: =SBC-MCM93; P/N: 170F10010
C5 = 100nF,_10V,_X7R,_10%,_0402: CLABCONF0: =SBC-MCM93; P/N: 151C10500S
C10 = 100nF,_10V,_X7R,_10%,_0402_7: CLABCONF0: =SBC-MCM93; Group: LAN2
C11 C140 C210 = 10uF,6_0.3V,0603,20%X5R: CLABCONF0: =SBC-MCM93
C15 = 100nF,_10V,_X7R,_10%,_0402_4: CLABCONF0: =SBC-MCM93; P/N: 151C10500S
C16 = 22uF,25V,_0805: CLABCONF0: =SBC-MCM93
C39 = 22uF,25V,_0805_1: CLABCONF0: =SBC-MCM93
C40 = 100nF,_10V,_X7R,_10%,_0402_8: CLABCONF0: =SBC-MCM93; P/N: 151C10500S
C139 = 100nF,_10V,_X7R,_10%,_0402_1: CLABCONF0: =SBC-MCM93; P/N: 151C10500S
C156 = 100nF,_10V,_X7R,_10%,_0402_2: CLABCONF0: =SBC-MCM93; Group: LAN2
C159 = 100nF,_10V,_X7R,_10%,_0402_3: CLABCONF0: =SBC-MCM93; Group: LAN2
C160 = 100nF,_10V,_X7R,_10%,_0402_6: CLABCONF0: =SBC-MCM93; Group: LAN2
C211 = 100nF,_10V,_X7R,_10%,_0402_5: CLABCONF0: =SBC-MCM93; P/N: 151C10500S
J2 J3 = USB_Conn.,_Fem,_Type_A_,_TH,_RA: CLABCONF0: =SBC-MCM93
L1 L2 L12 L13 L16 L22-L24 = ESD_CHOKE_DIFFx2_10: CLABCONF0: =SBC-MCM93; P/N: 142D11801S
P21 = Conn.,_Micro-USB,_B-Type: CLABCONF0: =SBC-MCM93; P/N: 180K00501S
R8 = 0R,_0402_5: CLABCONF0: DNP
R9 = 0R,_0402_6: CLABCONF0: DNP
R15 = 1M_,5%,_0402_2: CLABCONF0: =SBC-MCM93; P/N: 161C10021S
R16 = 0R,_0402_2: CLABCONF0: =SBC-MCM93
R17 = 1M_,5%,_0402_3: CLABCONF0: =SBC-MCM93; P/N: 161C10021S
R22 = 100K,_1%,_0402,_1_16W: CLABCONF0: =SBC-MCM93; P/N: 161C20031S
R23 = 0R,_0402_4: CLABCONF0: =SBC-MCM93
R33 R129 R230 = 10K,1%,0402,1_16W_0: CLABCONF0: =SBC-MCM93
R34 R117 R130 R174 = 0R,_0402_1: CLABCONF0: =SBC-MCM93
R36 R177 = RESISTOR: CLABCONF0: =SBC-MCM93; P/N: 161C14721S
R45 = 100K,_1%,_0402,_1_16W_1: CLABCONF0: =SBC-MCM93; P/N: 161C20031S
R60 = 1M_,5%,_0402_4: CLABCONF0: =SBC-MCM93; P/N: 161C10021S
R79 R223 = 0R,_0402: CLABCONF0: =SBC-MCM93
R87 = 1M_,5%,_0402: CLABCONF0: DNP; P/N: 161C10021S
R121 = 0R,_0402_3: CLABCONF0: =SBC-MCM93
R132 R171 = 10K,1%,0402,1_16W_0_1: CLABCONF0: =SBC-MCM93
R172 = 0R,_0402_7: CLABCONF0: =SBC-MCM93
R173 = 1M_,5%,_0402_1: CLABCONF0: =SBC-MCM93; P/N: 161C10021S
U4 U11 = RT9703,3A_Power_switch+FLG: CLABCONF0: =SBC-MCM93; P/N: 124S10080S
U5 U8 = Bus_switch_2_1: CLABCONF0: =SBC-MCM93
U7 = USB2_0.0_mux_v2: CLABCONF0: =SBC-MCM93; P/N: 116A72220S
U25 = USB2_0.0_mux: CLABCONF0: =SBC-MCM93; P/N: 116A72220S
C83 = 100nF,_10V,_X7R,_10%,_0402_13: CLABCONF0: =SBC-MCM93
C124 C136 = 100nF,_10V,_X7R,_10%,_0402_0: CLABCONF0: =SBC-MCM93
C132 = 100nF,_10V,_X7R,_10%,_0402_14: CLABCONF0: =SBC-MCM93
C196 = 10nF,_25V,_X7R,_10%,_0402: CLABCONF0: =SBC-MCM93
C197 = 100pF,_50V,_NPO,_5%,_0402: CLABCONF0: =SBC-MCM93
D3 D5 = BAT54WS_0: CLABCONF0: =SBC-MCM93
DS4 = LED-GREEN_1206_2: CLABCONF0: =SBC-MCM93
J4 = CON50A: CLABCONF0: =SBC-MCM93; P/N: 182K05001S
P9 P10 P15-P17 P19 P20 = HDR_2x7_100MIL_RA_TH_SHRD_0: CLABCONF0: =SBC-MCM93; P/N: 190C00801S
P11 P18 = HDR_2x5_100MIL_SMT: CLABCONF0: =SBC-MCM93
Q8 = P-MOS,_1.5A,_8V: CLABCONF0: DNP
Q4 Q9 = N-MOSFET_Dual: CLABCONF0: =SBC-MCM93; P/N: 131D31540S
Q11 = DUAL_N-MOSFET,_0.5A_20V: CLABCONF0: =SBC-MCM93
R77 = 10K,1%,0402,1_16W_1: CLABCONF0: =SBC-MCM93
R78 = 0R,_0402_1_20: CLABCONF0: DNP
R115 = 0R,_0402_1_7: CLABCONF0: =SBC-MCM93
R116 = 0R,_0402_1_18: CLABCONF0: =SBC-MCM93
R118 = 0R,_0402_1_13: CLABCONF0: =SBC-MCM93
R127 R159 = 0R,_0402_1_3: CLABCONF0: =SBC-MCM93
R128 = 0R,_0402_1_4: CLABCONF0: =SBC-MCM93
R133 R161 = 0R,_0402_1_2: CLABCONF0: =SBC-MCM93
R134 = 0R,_0402_1_14: CLABCONF0: DNP
R136 = 0R,_0402_1_9: CLABCONF0: =SBC-MCM93
R137 = 0R,_0402_1_22: CLABCONF0: =SBC-MCM93
R138 = 0R,_0402_1_16: CLABCONF0: =SBC-MCM93
R139 = 0R,_0402_1_5: CLABCONF0: =SBC-MCM93
R140 = 0R,_0402_1_15: CLABCONF0: =SBC-MCM93
R141 = 0R,_0402_1_17: CLABCONF0: =SBC-MCM93
R142 = 0R,_0402_1_6: CLABCONF0: =SBC-MCM93
R143 R160 = 0R,_0402_1_1: CLABCONF0: =SBC-MCM93
R144 = 10K,1%,0402,1_16W_0_3: CLABCONF0: =SBC-MCM93
R151 = 0R,_0402_1_11: CLABCONF0: =SBC-MCM93
R152 = 0R,_0402_1_10: CLABCONF0: =SBC-MCM93
R153 = 0R,_0402_1_12: CLABCONF0: DNP
R156 = 0R,_0402_1_8: CLABCONF0: DNP
R158 = 10K,1%,0402,1_16W_0_4: CLABCONF0: =SBC-MCM93
R188 = 0R,_0402_1_21: CLABCONF0: =SBC-MCM93
R189 = 10K,1%,0402,1_16W: CLABCONF0: =SBC-MCM93
R219 = 1K,1%,0402,1_16W: CLABCONF0: DNP; Group: CAN
R220 = 1K,1%,0402,1_16W_1: CLABCONF0: DNP; Group: CAN
R221 = 100R,1%,0402,1_16W: CLABCONF0: =SBC-MCM93
R222 = 220R,5%,0402,1_16W: CLABCONF0: =SBC-MCM93
R226 = 348R,1%,0402,1_16W_1: CLABCONF0: =SBC-MCM93; P/N: 161C20001S
R227 = 1K,1%,0402,1_16W_2: CLABCONF0: DNP; Group: CAN
R228 = 10K,1%,0402,1_16W_0_2: CLABCONF0: =SBC-MCM93
R229 = 348R,1%,0402,1_16W: CLABCONF0: =SBC-MCM93; P/N: 161C20001S
R231 = 0R,_0402_1_19: CLABCONF0: =SBC-MCM93
R233 = 0R,_0402_0: CLABCONF0: =SBC-MCM93; Group: Always; P/N: 161C12001S
RN2 = RN,10K,8P4R@0805: CLABCONF0: =SBC-MCM93
TP6 TP7 = TESTPOINT: CLABCONF0: DNP; P/N: 188Z01370S
U17 = PCA9555_1: CLABCONF0: =SBC-MCM93
U20 = 74AUP1G07_,_buffer_,LV: CLABCONF0: =SBC-MCM93
U21 = ATA6563: CLABCONF0: =SBC-MCM93; P/N: 116A00380S
C122 = 10uF,6.3V,0603,20%X5R: CLABCONF0: =SBC-MCM93
C195 = 1uF,X5R,6.3V,0402: CLABCONF0: =SBC-MCM93; P/N: 151D10510S
C207 = CAP_NP: CLABCONF0: =SBC-MCM93; P/N: 151C10611S; Part Name: Cap., 10uF, 25V, X5R/X7R, 20%, 0603
C209 = 1uF,X5R,6.3V,0402: CLABCONF0: =SBC-MCM93
D4 = ZENER_24V_500mW_SOD-123: CLABCONF0: DNP
L11 = INC_DELTA_SI43-100,_10uH: CLABCONF0: =SBC-MCM93; CLABCONF1: <null>
P12 = HDR_2x12_100MIL_0: CLABCONF0: =SBC-MCM93; P/N: 190C02000S
R131 = 0R,_0402_2: CLABCONF0: DNP
R154 = 2.2K,5%,0402.1_16W: CLABCONF0: =SBC-MCM93
R224 = 2.2R,5%,0402,1_16W: CLABCONF0: =SBC-MCM93; P/N: 161C00005S
R225 = 2.2R,5%,0402,1_16W_1: CLABCONF0: =SBC-MCM93; P/N: 161C06R25S
U18 = AIC1647_0: CLABCONF0: =SBC-MCM93; P/N: 123C40000S
C157 = Cap.,10uF,6.3V,0603,X5R: CLABCONF0: =SBC-MCM93
C158 = Cap.,10uF,6.3V,0603,X5R_1: CLABCONF0: =SBC-MCM93
P5 P6 = Con_0.,1GBit_RJ45,_short: CLABCONF0: =SBC-MCM93
R162 = 475R_1%,_0402_3: CLABCONF0: =SBC-MCM93
R163 = 475R_1%,_0402: CLABCONF0: =SBC-MCM93
R164 = 475R_1%,_0402_2: CLABCONF0: =SBC-MCM93
R165 = 475R_1%,_0402_1: CLABCONF0: =SBC-MCM93

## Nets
3V3_EXP: C121.1 Q8.3(D) R188.1 U17.21(VDD)
GND: C5.1 C10.1 C11.2 C13.2 C15.1 C16.2 C18.2 C19.2 C39.2 C40.1 C62.2 C69.2 C70.2 C75.2 C76.2 C77.2 C81.2 C82.2 C83.2 C84.2 C86.2 C87.1 C88.2 C89.1 C90.2 C97.1 C98.2 C106.2 C115.2 C121.2 C122.2 C123.2 C124.1 C125.2 C126.2 C128.2 C132.2 C134.1 C135.2 C136.2 C139.1 C140.2 C149.2 C150.2 C154.2 C155.2 C156.1 C157.2 C158.2 C159.1 C160.1 C187.1 C188.2 C191.1 C192.1 C195.2 C197.2 C200.2 C201.2 C202.2 C203.2 C204.2 C205.2 C209.1 C210.2 C211.1 D1.ANODE DS2.CATHODE E1.2 J1.2(R) J1.SH1 J1.SH2 J1.SH3 J1.SH4 J2.4(GND) J2.5(SHELL_1) J2.6(SHELL_2) J3.4(GND) J3.5(SHELL_1) J3.6(SHELL_2) J4.1 J4.2 J4.7 J4.8 J4.14 J4.25 J4.26 J4.31 J4.32 J4.37 J4.38 J4.44 L1.5(GND) L1.6(GND) L2.5(GND) L2.6(GND) L12.5(GND) L12.6(GND) L13.5(GND) L13.6(GND) L16.5(GND) L16.6(GND) L22.5(GND) L22.6(GND) L23.5(GND) L23.6(GND) L24.5(GND) L24.6(GND) MCM93_MOD1.75(5) MCM93_MOD1.G1(GND_PAD1) MCM93_MOD1.G2(GND_PAD2) MCM93_MOD1.G3(GND_PAD3) MCM93_MOD1.G4(GND_PAD4) MCM93_MOD1.G5(GND_PAD5) MCM93_MOD1.G6(GND_PAD6) MCM93_MOD1.G7(GND_PAD7) MCM93_MOD1.G8(GND_PAD8) MCM93_MOD1.G9(GND_PAD9) MCM93_MOD1.G10(GND_PAD10) MCM93_MOD1.G11(GND_PAD11) MCM93_MOD1.G12(GND_PAD12) MCM93_MOD1.G13(GND_PAD13) MCM93_MOD1.G14(GND_PAD14) MCM93_MOD1.G15(GND_PAD15) MCM93_MOD1.G16(GND_PAD16) MCM93_MOD1.G17(GND_PAD17) MCM93_MOD1.G18(GND_PAD18) MCM93_MOD1.G19(GND_PAD19) MCM93_MOD1.G20(GND_PAD20) MCM93_MOD1.G21(GND_PAD21) MCM93_MOD1.G22(GND_PAD22) MCM93_MOD1.G23(GND_PAD23) MCM93_MOD1.G24(GND_PAD24) MCM93_MOD1.G25(GND_PAD25) MCM93_MOD1.G26(GND_PAD26) MCM93_MOD1.G27(GND_PAD27) MCM93_MOD1.G28(GND_PAD28) P5.S1(SHIELD) P5.S2(SHIELD) P6.S1(SHIELD) P6.S2(SHIELD) P9.8 P10.8 P11.4 P11.6 P12.1 P12.2 P12.7 P12.8 P12.13 P12.14 P15.8 P16.8 P17.8 P18.10 P19.8 P20.8 P21.5(GND) P21.6(SHIELD1) P21.7(SHIELD2) P21.8(SHIELD3) P21.9(SHIELD4) Q2.2(SOURCE) Q3.2(SOURCE) Q4.1(S) Q5.2(SOURCE) Q6.2(SOURCE) Q7.2(SOURCE) Q9.1(S) Q11.1(S1) Q11.4(S2) R16.1 R22.2 R33.1 R36.2 R37.2 R45.2 R77.2 R87.1 R121.2 R151.1 R154.2 R158.1 R171.1 R177.2 R222.2 R224.2 R228.1 R230.1 RN2.2(RB1) RN2.3(RC1) RN2.4(RD1) SW1.1 SW3.1 SW3.3 SW4.1 SW4.3 U4.4(GND) U5.2(GND) U7.4(GND) U8.2(GND) U11.4(GND) U17.9(VSS) U17.25(CPAD) U18.2(GND) U20.3(GND) U21.2(GND) U25.4(GND) ; also on sheet 8 9 10 11 12 13 14
VBUS_USB_A: C5.2 C11.1 C39.1 J3.1(VBUS) R9.1 R24.1 U11.2(Vout) U11.3(Vout)
VBUS_USB_B: C16.1 C210.1 C211.2 J2.1(VBUS) R8.1 U4.2(Vout) U4.3(Vout)
VCC_1V8: C83.1 C115.1 C126.1 J4.13 J4.49 P9.1 R96.1 R97.1 R152.1 ; also on sheet 8 11 12 14
VCC_3V3: C10.2 C84.1 C106.1 C128.1 C135.1 C136.1 C160.2 C200.1 C201.1 C202.1 C204.1 C205.1 C209.2 DS4.ANODE DS5.ANODE E3.2 J4.20 J4.50 P10.1 P12.20 P15.1 P16.1 P18.1 P19.1 P20.1 Q8.2(S) R15.2 R17.2 R39.1 R40.1 R60.2 R130.1 R132.1 R153.2 R159.1 R160.1 R161.1 R174.1 R188.2 R189.2 R219.1 R220.1 R227.1 SW2.1 SW2.3 U7.9(VCC) U21.5(VIO) U25.9(VCC) ; also on sheet 8 9 10 11 12 13 14
VCC_5V0: C15.2 C40.2 C124.2 C125.1 C156.2 C159.2 C203.1 P17.1 R98.1 R99.1 U4.6(Vin) U4.7(Vin) U5.5(VCC) U8.5(VCC) U11.6(Vin) U11.7(Vin) U21.3(VCC) ; also on sheet 9 11 14
VCC_RTC: MCM93_MOD1.127(22) ; also on sheet 11
ADC_IN0: MCM93_MOD1.10 P9.2
ADC_IN1: MCM93_MOD1.9 P9.4
ADC_IN2: MCM93_MOD1.8 P9.6
ADC_IN3: MCM93_MOD1.7 P9.3
ALT_BOOT: MCM93_MOD1.76(6) R64.1
CAN1_H: P17.2 R233.2 U21.7(CANH)
CAN1_L: E6.1 P17.6 R156.2 U21.6(CANL)
CAN_STBY: R158.2 U21.8(STBY)
CAN_T: E6.2 R156.1 R233.1
CARRIER_3V3_GPIO0_0: R136.2 U17.1(I/O0.0)
CARRIER_3V3_GPIO0_1: R137.2 U17.2(I/O0.1)
CARRIER_3V3_GPIO0_2: R138.2 U17.3(I/O0.2)
CARRIER_3V3_GPIO0_3: R139.2 U17.4(I/O0.3)
CARRIER_3V3_GPIO0_4: R140.2 U17.5(I/O0.4)
CARRIER_3V3_GPIO0_5: R141.2 U17.6(I/O0.5)
CARRIER_3V3_GPIO0_6: R142.2 U17.7(I/O0.6)
CARRIER_3V3_GPIO0_7: TP7.1 U17.8(I/O0.7)
CARRIER_3V3_GPIO1_0: R133.2 U17.10(I/O1.0)
CARRIER_3V3_GPIO1_1: R128.2 U17.11(I/O1.1)
CARRIER_3V3_GPIO1_2: R127.2 U17.12(I/O1.2)
CARRIER_3V3_GPIO1_3: R118.2 U17.13(I/O1.3)
CARRIER_3V3_GPIO1_4: R117.2 U17.14(I/O1.4)
CARRIER_3V3_GPIO1_5: R116.2 U17.15(I/O1.5)
CARRIER_3V3_GPIO1_6: R115.2 U17.16(I/O1.6)
CARRIER_3V3_GPIO1_7: TP6.1 U17.17(I/O1.7)
CSI1_CONTR: J4.19 R137.1
CSI1_FLASH_OUT: J4.23 R127.1
CSI1_PWR_DWN: J4.22 R133.1
CSI1_RST: J4.24 R128.1
CSI1_TRG: J4.21 R118.1
CSI_CLK_N: J4.5 MCM93_MOD1.18
CSI_CLK_P: J4.3 MCM93_MOD1.19
CSI_D0_N: J4.6 MCM93_MOD1.21
CSI_D0_P: J4.4 MCM93_MOD1.20
CSI_D1_N: J4.11 MCM93_MOD1.23
CSI_D1_P: J4.9 MCM93_MOD1.22
DC_FLT: C12.1 FB1.2 FB2.2 Q1.1(S) Q1.2(S) Q1.3(S) R2.2 R13.2
DC_IN_LED: DS2.ANODE R2.1
DC_JACK: C13.1 D1.CATHODE FB1.1 FB2.1 J1.1(CENTRAL)
DISCH_ON_H: Q2.1(GATE) Q3.1(GATE) Q5.1(GATE) Q6.1(GATE) Q7.1(GATE) R26.2 R37.1
DISCH_ONH: R21.2 R26.1 SW1.2
DS3_G#: Q11.3(D2) R226.1
DS3_R#: Q11.6(D1) R229.1
DS4_G: DS4.CATHODE R229.2
DS5_Y: DS5.CATHODE R226.2
DSI1_CN: L13.1 P12.5
DSI1_CP: L13.2 P12.3
DSI1_N0: L22.1 P12.6
DSI1_N1: L12.1 P12.11
DSI1_N2: L23.1 P12.12
DSI1_N3: L24.1 P12.18
DSI1_P0: L22.2 P12.4
DSI1_P1: L12.2 P12.9
DSI1_P2: L23.2 P12.10
DSI1_P3: L24.2 P12.16
DSI_BCKLIGHT_FB: D4.2(ANODE) R223.2 U18.3(FB)
DSI_BCKLIGHT_IN: C122.1 C123.1 L11.1 R129.1 R130.2 U18.6(IN)
DSI_CLK_N: L13.4 MCM93_MOD1.24
DSI_CLK_P: L13.3 MCM93_MOD1.25
DSI_D0_N: L22.4 MCM93_MOD1.32
DSI_D0_P: L22.3 MCM93_MOD1.33
DSI_D1_N: L12.4 MCM93_MOD1.30
DSI_D1_P: L12.3 MCM93_MOD1.31
DSI_D2_N: L23.4 MCM93_MOD1.28
DSI_D2_P: L23.3 MCM93_MOD1.29
DSI_D3_N: L24.4 MCM93_MOD1.27
DSI_D3_P: L24.3 MCM93_MOD1.26
DSI_DISP_RESET: P12.17 R140.1 R154.1
DSI_LED_A: C195.1 C207.2 D4.1(CATHODE) D5.CATHODE P12.19 U18.5(OVP)
DSI_LED_EN: R129.2 R131.2 U18.4(EN/PWM)
DSI_LED_K: C207.1 P12.15 R223.1 R225.1
DSI_WLD_RES: R224.1 R225.2
DSI_WLD_SW: D5.ANODE L11.2 U18.1(LX)
ECSPI3_MISO/UART7_RX: MCM93_MOD1.121(16) P15.2
ECSPI3_MOSI: MCM93_MOD1.123(18) P15.3
ECSPI3_SCLK: MCM93_MOD1.122(17) P15.5
ECSPI3_SS0/UART7_TX: MCM93_MOD1.120(15) P15.4
ECSPI4_MOSI/GPIO2_20: MCM93_MOD1.116(11) ; also on sheet 9
ECSPI4_SCLK/GPIO2_21: MCM93_MOD1.117(12) P18.3
ENET1_MDC: MCM93_MOD1.94(24) ; also on sheet 8
ENET1_MDIO: MCM93_MOD1.93(23) ; also on sheet 8
ENET1_RD0: MCM93_MOD1.88(18) ; also on sheet 8
ENET1_RD1: MCM93_MOD1.90(20) ; also on sheet 8
ENET1_RD2: MCM93_MOD1.91(21) ; also on sheet 8
ENET1_RD3: MCM93_MOD1.92(22) ; also on sheet 8
ENET1_RX_CTL: MCM93_MOD1.87(17) ; also on sheet 8
ENET1_RXC: MCM93_MOD1.89(19) ; also on sheet 8
ENET1_TD0: MCM93_MOD1.84(14) ; also on sheet 8
ENET1_TD1: MCM93_MOD1.82(12) ; also on sheet 8
ENET1_TD2: MCM93_MOD1.83(13) ; also on sheet 8
ENET1_TD3: MCM93_MOD1.85(15) ; also on sheet 8
ENET1_TX_CTL: MCM93_MOD1.81(11) ; also on sheet 8
ENET1_TXC: MCM93_MOD1.86(16) ; also on sheet 8
ENET2_MDC: MCM93_MOD1.50(15) ; also on sheet 8
ENET2_MDIO: MCM93_MOD1.49(14) ; also on sheet 8
ENET2_RD0: MCM93_MOD1.59(24) ; also on sheet 8
ENET2_RD1: MCM93_MOD1.60(25) ; also on sheet 8
ENET2_RD2: MCM93_MOD1.61(26) ; also on sheet 8
ENET2_RD3: MCM93_MOD1.62(27) ; also on sheet 8
ENET2_RX_CTL: MCM93_MOD1.58(23) ; also on sheet 8
ENET2_RXC: MCM93_MOD1.57(22) ; also on sheet 8
ENET2_TD0: MCM93_MOD1.52(17) ; also on sheet 8
ENET2_TD1: MCM93_MOD1.53(18) ; also on sheet 8
ENET2_TD2: MCM93_MOD1.55(20) ; also on sheet 8
ENET2_TD3: MCM93_MOD1.51(16) ; also on sheet 8
ENET2_TX_CTL: MCM93_MOD1.54(19) ; also on sheet 8
ENET2_TXC: MCM93_MOD1.56(21) ; also on sheet 8
ETH1_CT1A: C155.1 C158.1 P5.P5(CT)
ETH1_CT2A: C150.1 P5.P6(CT)
ETH1_GREEN_LED_AN: P5.P12(LED1_A) R160.2
ETH1_GREEN_LED_CAT: P5.P11(LED1_C) R164.1
ETH1_LED0/CFG_EXT: R164.2 ; also on sheet 8
ETH1_LED2/CFG_LDO1: R165.2 ; also on sheet 8
ETH1_MDI0N: P5.P2(MDI0-) ; also on sheet 8
ETH1_MDI0P: P5.P1(MDI0+) ; also on sheet 8
ETH1_MDI1N: P5.P4(MDI1-) ; also on sheet 8
ETH1_MDI1P: P5.P3(MDI1+) ; also on sheet 8
ETH1_MDI2N: P5.P8(MDI2-) ; also on sheet 8
ETH1_MDI2P: P5.P7(MDI2+) ; also on sheet 8
ETH1_MDI3N: P5.P10(MDI3-) ; also on sheet 8
ETH1_MDI3P: P5.P9(MDI3+) ; also on sheet 8
ETH1_YELLOW_LED_AN: P5.P14(LED2_A) R161.2
ETH1_YELLOW_LED_CAT: P5.P13(LED2_C) R165.1
ETH2_CT1A: C154.1 C157.1 P6.P5(CT)
ETH2_CT2A: C149.1 P6.P6(CT)
ETH2_GREEN_LED_AN: P6.P12(LED1_A) R174.2
ETH2_GREEN_LED_CAT: P6.P11(LED1_C) R162.1
ETH2_LED0/CFG_EXT: R162.2 ; also on sheet 8
ETH2_LED2/CFG_LDO1: R163.2 ; also on sheet 8
ETH2_MDI0N: P6.P2(MDI0-) ; also on sheet 8
ETH2_MDI0P: P6.P1(MDI0+) ; also on sheet 8
ETH2_MDI1N: P6.P4(MDI1-) ; also on sheet 8
ETH2_MDI1P: P6.P3(MDI1+) ; also on sheet 8
ETH2_MDI2N: P6.P8(MDI2-) ; also on sheet 8
ETH2_MDI2P: P6.P7(MDI2+) ; also on sheet 8
ETH2_MDI3N: P6.P10(MDI3-) ; also on sheet 8
ETH2_MDI3P: P6.P9(MDI3+) ; also on sheet 8
ETH2_YELLOW_LED_AN: P6.P14(LED2_A) R159.2
ETH2_YELLOW_LED_CAT: P6.P13(LED2_C) R163.1
EXP_nPWREN: Q9.2(G) R77.1 R78.2
EXP_nPWREN_G: Q8.1(G) Q9.6(D) R189.1
EXPANDER_A0: R227.2 RN2.5(RD2) U17.18(A0)
EXPANDER_A1: R220.2 RN2.6(RC2) U17.23(A1)
EXPANDER_A2: R219.2 RN2.7(RB2) U17.24(A2)
GPIO2_19/TPM6_CH2: MCM93_MOD1.119(14) R131.1
GPIO24: P18.5 R231.2
GPIO_CONTR1: P18.4 R136.1
GPIO_CONTR2: P18.6 R117.1
GPIO_IO00/UART5_TXD: MCM93_MOD1.129(24) P20.4
GPIO_IO01/UART5_RXD: MCM93_MOD1.45(10) P20.2
GPIO_IO02/UART5_CTS: MCM93_MOD1.128(23) P20.6
GPIO_IO03/UART5_RTS: MCM93_MOD1.108(3) P20.3
GPIO_IO04/I2C6_SDA: MCM93_MOD1.125(20) P16.3
GPIO_IO05/I2C6_SCL: MCM93_MOD1.124(19) P16.5
GPIO_IO06: MCM93_MOD1.107(2) ; also on sheet 8
GPIO_IO07: MCM93_MOD1.106(1) ; also on sheet 8
GPIO_IO12: MCM93_MOD1.105(35) ; also on sheet 8
GPIO_IO13/TPM4_CH2: MCM93_MOD1.104(34) ; also on sheet 9
GPIO_IO14/UART3_TX: MCM93_MOD1.102(32) P19.4
GPIO_IO15/UART3_RX: MCM93_MOD1.103(33) P19.2
GPIO_IO16: MCM93_MOD1.101(31) ; also on sheet 8
GPIO_IO17: MCM93_MOD1.100(30) ; also on sheet 12
GPIO_IO18/TPM_CH2: MCM93_MOD1.118(13) P18.2
GPIO_IO22/TPM5_CH1: MCM93_MOD1.115(10) P18.9
GPIO_IO23/SPDIF_TX: C196.2 MCM93_MOD1.96(26)
GPIO_IO24: MCM93_MOD1.99(29) R231.1 ; also on sheet 14
GPIO_IO25/CAN2_TX: MCM93_MOD1.95(25) U21.1(TXD)
GPIO_IO26: MCM93_MOD1.47(12) P18.7 R78.1
GPIO_IO27/CAN2_RX: MCM93_MOD1.48(13) U21.4(RXD)
HASW_EN: E1.1 R15.1 U4.5(EN) U7.10(SEL)
HASW_IP1: R45.1 U11.8(IP)
HASW_IP2: R22.1 U4.8(IP)
HOSTA_USB_DN: J3.2(D-) L1.4
HOSTA_USB_DP: J3.3(D+) L1.3
HOSTB_USB_DN: J2.2(D-) L2.4
HOSTB_USB_DP: J2.3(D+) L2.3
HUB_OE: R33.2 U7.8(\\~{O}E)
I2C3_SCK: MCM93_MOD1.97(27) ; also on sheet 10
I2C3_SCL_CM: J4.15 U17.19(SCL) ; also on sheet 9 10 14
I2C3_SDA: MCM93_MOD1.98(28) ; also on sheet 10
I2C3_SDA_CM: J4.17 U17.20(SDA) ; also on sheet 9 10 14
ID_VBUS_SEL: R35.2 R36.1 U5.6(SEL) U8.6(SEL)
INT_EXP: R132.2 U17.22(\\~{IN}T)
JTAG_HDR_10: P11.10 R151.2
JTAG_POWER: C132.1 C134.2 D3.ANODE P11.2 R152.2 R153.1 U20.5(VCC)
JTAG_RST: P11.9 R144.2 U20.2(IN)
JTAG_RST_PU: D3.CATHODE R144.1
JTAG_TCK: MCM93_MOD1.79(9) P11.3
JTAG_TDI: MCM93_MOD1.77(7) P11.7
JTAG_TDO: MCM93_MOD1.80(10) P11.5
JTAG_TMS: MCM93_MOD1.78(8) P11.1
JTAGRST_OD: R134.1 R143.1 U20.4(OUT)
LVDS_CLK_N: MCM93_MOD1.38(3) ; also on sheet 9
LVDS_CLK_P: MCM93_MOD1.39(4) ; also on sheet 9
LVDS_DISP_RESET: R142.1 ; also on sheet 9
LVDS_TX0_N: MCM93_MOD1.34 ; also on sheet 9
LVDS_TX0_P: MCM93_MOD1.35 ; also on sheet 9
LVDS_TX1_N: MCM93_MOD1.36(1) ; also on sheet 9
LVDS_TX1_P: MCM93_MOD1.37(2) ; also on sheet 9
LVDS_TX2_N: MCM93_MOD1.40(5) ; also on sheet 9
LVDS_TX2_P: MCM93_MOD1.41(6) ; also on sheet 9
LVDS_TX3_N: MCM93_MOD1.42(7) ; also on sheet 9
LVDS_TX3_P: MCM93_MOD1.43(8) ; also on sheet 9
MODEM_RST: R116.1 ; also on sheet 10
mux_PCIe_USB_DN: U7.7(HSD1-) ; also on sheet 10
mux_PCIe_USB_DP: U7.1(HSD1+) ; also on sheet 10
MUX_USB1_DN: L1.1 U25.7(HSD1-)
MUX_USB1_DP: L1.2 U25.1(HSD1+)
MUX_USB2_DN: L2.1 U7.6(HSD2-)
MUX_USB2_DP: L2.2 U7.2(HSD2+)
MUX_USB3_SEL: Q4.2(G) R79.2 R87.2
PB_ALT_BOOT: E3.1 R64.2 SW2.2 SW2.4
PB_RESET: R91.2 SW3.2 SW3.4
PB_SDWN_ENH: E4.2 R94.1
PMIC_ON_REQ: MCM93_MOD1.44(9) P10.6 ; also on sheet 11
PMIC_STBY_REQ: MCM93_MOD1.16 P10.4 ; also on sheet 11
POR_B_3P3: MCM93_MOD1.46(11) P10.5 R134.2
PWRBTN: MCM93_MOD1.3 R95.1
Q2_D: Q2.3(DRAIN) R38.2 R49.2
Q3_D: Q3.3(DRAIN) R39.2 R40.2
Q5_D: Q5.3(DRAIN) R85.2 R86.2
Q6_D: Q6.3(DRAIN) R96.2 R97.2
Q7_D: Q7.3(DRAIN) R98.2 R99.2
RF_KILL#: R115.1 ; also on sheet 10
SAI1_RXD0: MCM93_MOD1.131(26) ; also on sheet 14
SAI1_TXC/CAN1_RX: MCM93_MOD1.132(27) ; also on sheet 14
SAI1_TXD0/CAN1_TX: MCM93_MOD1.66(31) ; also on sheet 14
SAI1_TXFS: MCM93_MOD1.126(21) ; also on sheet 14
SD2_CLK: MCM93_MOD1.70(35) ; also on sheet 10
SD2_CMD: MCM93_MOD1.69(34) ; also on sheet 10
SD2_DATA0: MCM93_MOD1.72(2) ; also on sheet 10
SD2_DATA1: MCM93_MOD1.73(3) ; also on sheet 10
SD2_DATA2: MCM93_MOD1.68(33) ; also on sheet 10
SD2_DATA3: MCM93_MOD1.67(32) ; also on sheet 10
SD2_nCD: MCM93_MOD1.74(4) ; also on sheet 10
SD2_nRST: MCM93_MOD1.65(30) TP1.1
SD3_CLK: MCM93_MOD1.109(4) ; also on sheet 12
SD3_CMD: MCM93_MOD1.113(8) ; also on sheet 12
SD3_DATA0: MCM93_MOD1.114(9) ; also on sheet 12
SD3_DATA1: MCM93_MOD1.112(7) ; also on sheet 12
SD3_DATA2: MCM93_MOD1.110(5) ; also on sheet 12
SD3_DATA3: MCM93_MOD1.111(6) ; also on sheet 12
SDWN_ENH: E4.1 MCM93_MOD1.5
SPDIF_AUDIO_OUT: C197.1 P10.2 R221.2 R222.1
SPDIF_OUT1C: C196.1 R221.1
SWPWRBTN: R95.2 SW4.2 SW4.4
SYS_RST_PMIC: MCM93_MOD1.14 P10.3 R91.1 R143.2
TOUCH_RESET: R141.1 ; also on sheet 9
TP2: MCM93_MOD1.17 TP2.1
U5_IN0: R16.2 U5.3(B0)
U5_OUT: R23.1 U5.4(A)
U8_IN0: R24.2 U8.3(B0)
U8_IN1: R25.2 U8.1(B1)
U8_OUT: R34.1 U8.4(A)
U11_EN: Q4.6(D) R60.1 U11.5(EN)
U25_OEL: R171.2 U25.8(\\~{O}E)
UART1_RXD: MCM93_MOD1.64(29) ; also on sheet 10
UART1_TXD: MCM93_MOD1.63(28) ; also on sheet 10
UART2_RXD/GPIO1_IO6/SAI1_MCLK: MCM93_MOD1.133(28) ; also on sheet 14
UART2_TXD: MCM93_MOD1.130(25) P18.8
USB1_DN: MCM93_MOD1.140(35) U25.5(D-)
USB1_DP: MCM93_MOD1.139(34) U25.3(D+)
USB1_ID: MCM93_MOD1.1 R23.2
USB1_SEL: R172.1 U25.10(SEL)
USB1_VBUS_3V3: MCM93_MOD1.2 R9.2 R34.2
USB1SEL: R172.2 R173.1 R177.1
USB2_DN: MCM93_MOD1.137(32) U7.5(D-)
USB2_DP: MCM93_MOD1.136(31) U7.3(D+)
USB2_ID: MCM93_MOD1.135(30) R121.1
USB2_VBUS_3V3: MCM93_MOD1.138(33) R8.2
USB_SDM_DN: L16.1 U25.6(HSD2-)
USB_SDM_DP: L16.2 U25.2(HSD2+)
USBSD_VBUS: C139.2 C140.1 P21.1(VBUS) R25.1 R35.1 R79.1 R94.2 R173.2
USBSDM_DN: L16.4 P21.2(D-)
USBSDM_DP: L16.3 P21.3(D+)
User_LED1: Q11.2(G1) R138.1 R230.2
User_LED2: Q11.5(G2) R139.1 R228.2
uUSB_ID: P21.4(ID) R17.1 U5.1(B1)
V_SOM: C62.1 C69.1 C70.1 C75.1 C76.1 C77.1 C81.1 C82.1 C86.1 C87.2 C88.1 C89.2 C90.1 C97.2 C98.1 C187.2 C188.1 C191.2 C192.2 MCM93_MOD1.4 MCM93_MOD1.6 MCM93_MOD1.11 MCM93_MOD1.15 R85.1 R86.1 ; also on sheet 11 13
VDC_IN: C18.1 C19.1 Q1.5(D) Q1.6(D) Q1.7(D) Q1.8(D) Q1.9(D-pad) R38.1 R49.1 ; also on sheet 11
VGS_Q5: C12.2 Q1.4(G) R13.1 R21.1
VSD_3V3: MCM93_MOD1.134(29) ; also on sheet 10

Not connected (* = marked no-connect by the designer): J4 10* 12* 16* 18* 27* 28* 29* 30* 33* 34* 35* 36* 39* 40* 41* 42* 43* 45* 46* 47* 48*; MCM93_MOD1 12* 13* 71(1); P9 5* 7*; P10 7; P11 8*; P15 6* 7*; P16 2* 4* 6* 7*; P17 3* 4* 5* 7*; P19 3* 5* 6* 7*; P20 5* 7*; RN2 1(RA1)* 8(RA2)*; U4 1(FLG)*; U11 1(FLG)*

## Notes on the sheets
sheet 1
- 100 Ohm
- 100 Ohm
- 100 Ohm
- Ethernet 1 connector
- 100 Ohm
- 100 Ohm
- 100 Ohm
- 100 Ohm
- Ethernet 2 connector
- 100 Ohm
sheet 2
- SBC-MCM93
- BOARD REVISION: 1.0
- Page
- Description
- 01
- Index and Block Diagram
- 02
- MCM Connectors
- 03
- DC INP, Discharge
- 04
- USB
- 05
- JTAG, SPDIF,CAN, CSI,MISC
- 06
- Codec
- 07
- MIPI-DSI LCD
- 08
- LVDS LCD
- 09
- GBE
- 10
- Ethernet connectos
- 11
- Console, RS232, SD, miniPCIe
- 12
- WIFI&Bluetooth
- 13
- Power
- 14
- Mechanical
sheet 3
- DC input
- Vin 8V-18V
  Imax (vin=10V) =3.31A
- Discharge
- P-MOSFET, 8.3A, 20V
- 3A, 20V
sheet 4
- Serial Download
- Power button
- RESET
- PWM for U13 in SB
- Tamper
- SD boot
- SDP (USB) boot
- 10K PD  on the Module
- PWM for U18 in SB
- A53 core debug
- MCM connectors
sheet 5
- USB1
- Mux for USB1 ID and VBUS
- Host with mux for SDP mode
- DNP
- NOTE: USB1 multiplexing is controlled by presence of VBUS on connector P21
- 90 ohm
- # 90-Ohm differential pairs
- # 90-Ohm diff pairs
- Assembly ACAP to L23
- 1.05A LIMIT
- Serial Download mode
  (microUSB2.0 Type B)
- DNP
- USB2
- Host with mux for miniPCIe socket P8
- NOTE: USB1 multiplexing is controlled by jumper E1
- # 90-Ohm diff pairs
- 1.05A LIMIT
- E1 operation
  Open:       for USB conn. J2
  Close:      for miniPCIe socket P8
sheet 6
- JTAG
- CAN bus
- NXP refdes layout
- TMS
- VCC
- TCK
- GND
- TDI
- TDO
- GND
- DNP
- DNP
- DNP
- User LEDs
- System /Miscellaneous
- GPIO expander reset
- DNP
- Camera Edge Connector
- DNP
- CSI_D2_P
- CSI_D2_N
- CSI1
- CSI_D3_P
- CSI_D3_N
- CSIB_CLK_P
- CSIB_D0_P
- CSIB_CLK_N
- CSIB_D0_N
- CSIB_D1_P
- CSIB_D2_P
- CSI2
- CSIB_D1_N
- CSIB_D2_N
- I2C_SCL
- I2C_SDA
- CSIB_D3_N
- CSIB_D3_P
- CONTROL_B
- CONTROL_B
- CONTROL_B
- GPIO expander
- CONTROL_B
- CONTROL_B
- DNP
- DNP
- DNP
- UART
- I2C Address:
  0x20
- UART5_RXD
- UART5_CTS
- UART5_TXD
- UART5_RTS
- ADC/TPM (PWM)
- I2C
- GPIO
- ECSPI
- UART7_RX
- UART7_TX
- Output only
sheet 7
- MIPI-DSI LCD Int.
- # 100-Ohm diff pairs
- # 100-Ohm diff pairs
- MIPI LCD back-light power
- Typical LED configuration: Two parallel
  chains of 6 serially connected LEDs
- 19.2V/40mA
- DNP
